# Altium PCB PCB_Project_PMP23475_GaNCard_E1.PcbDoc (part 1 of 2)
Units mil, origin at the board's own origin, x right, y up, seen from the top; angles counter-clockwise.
Board outline 1635 x 1330 mil, 6 copper layers (Top Layer, MidLayer1, MidLayer2, MidLayer3, MidLayer4, Bottom Layer), stack 78 mil thick; 80 components, 70 nets, 296 pads, 209 vias.
Unrouted connection lines stored in the file: 3.
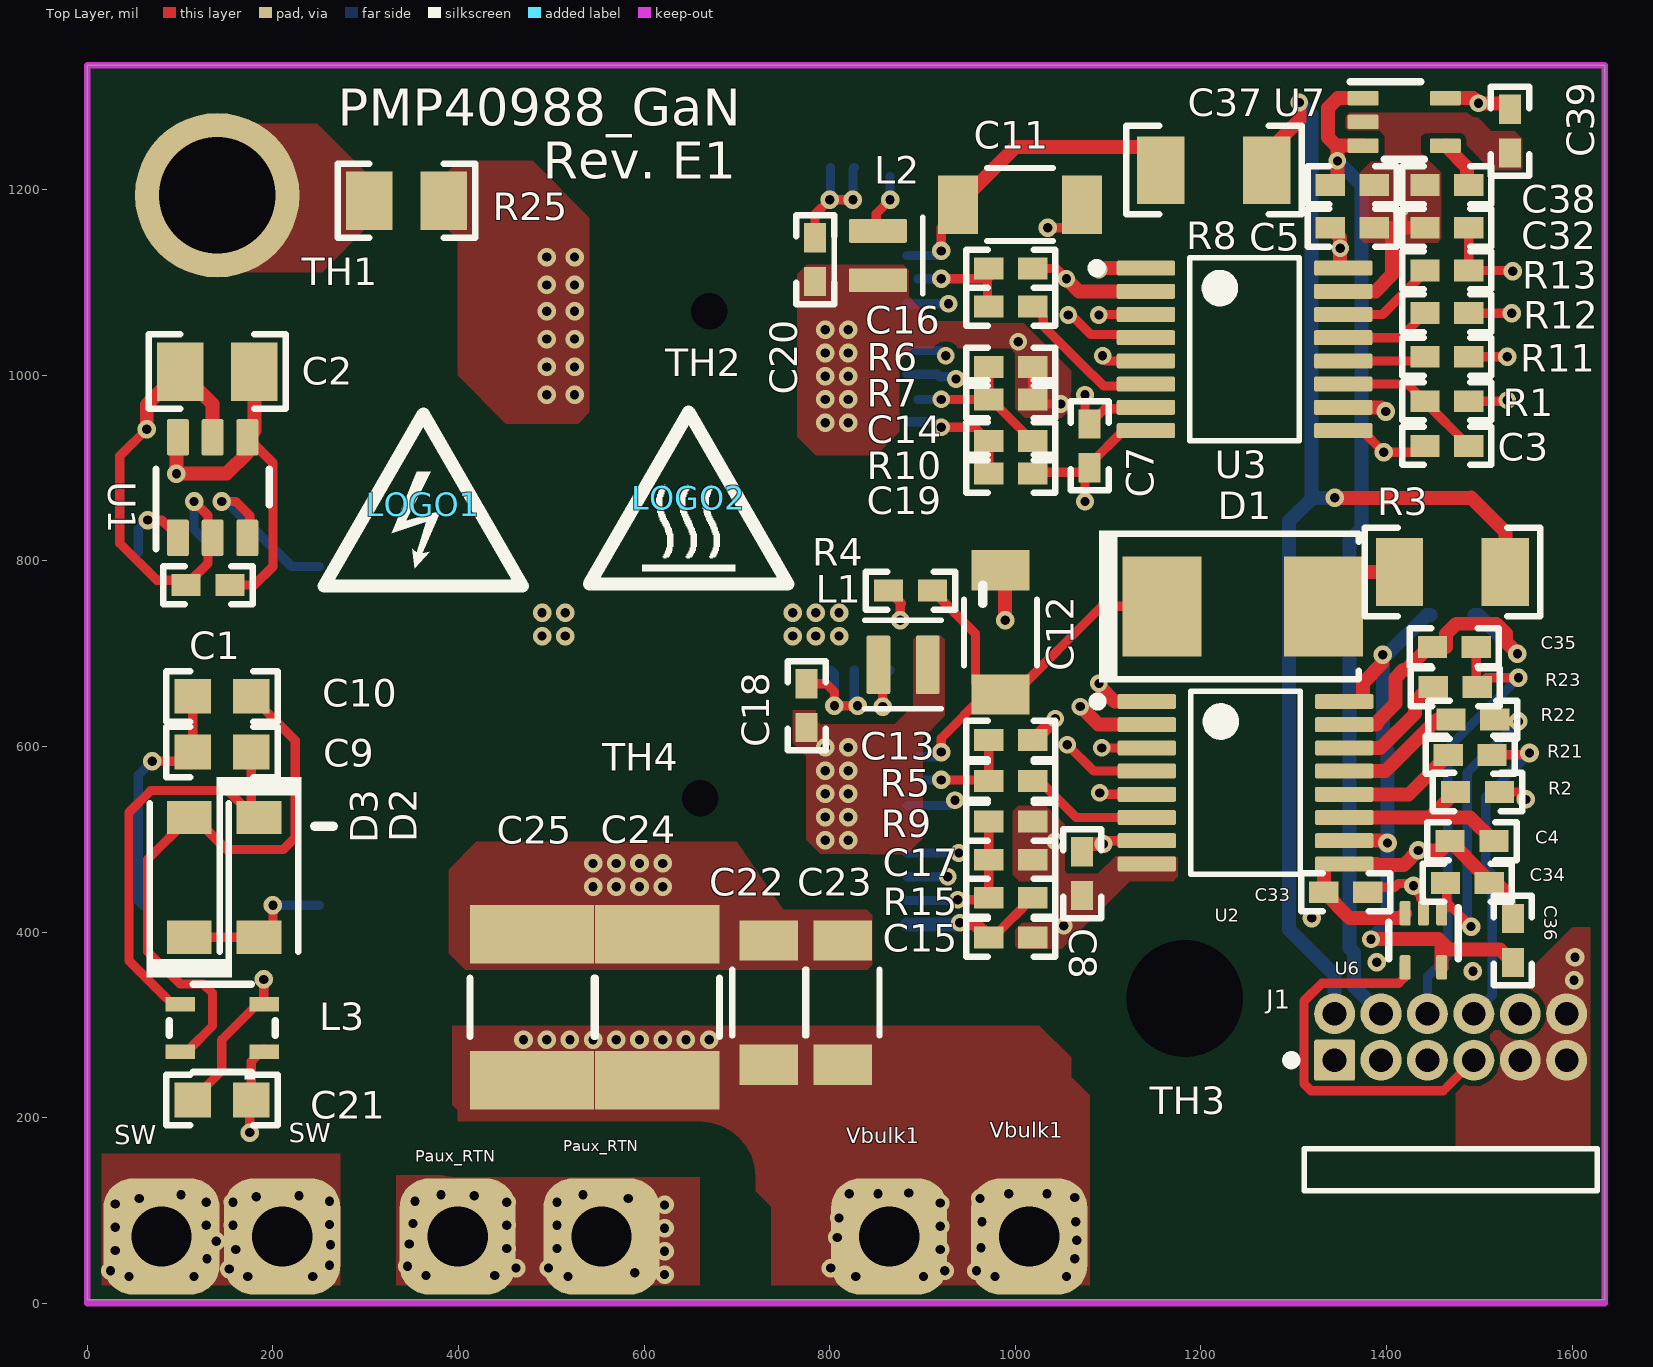
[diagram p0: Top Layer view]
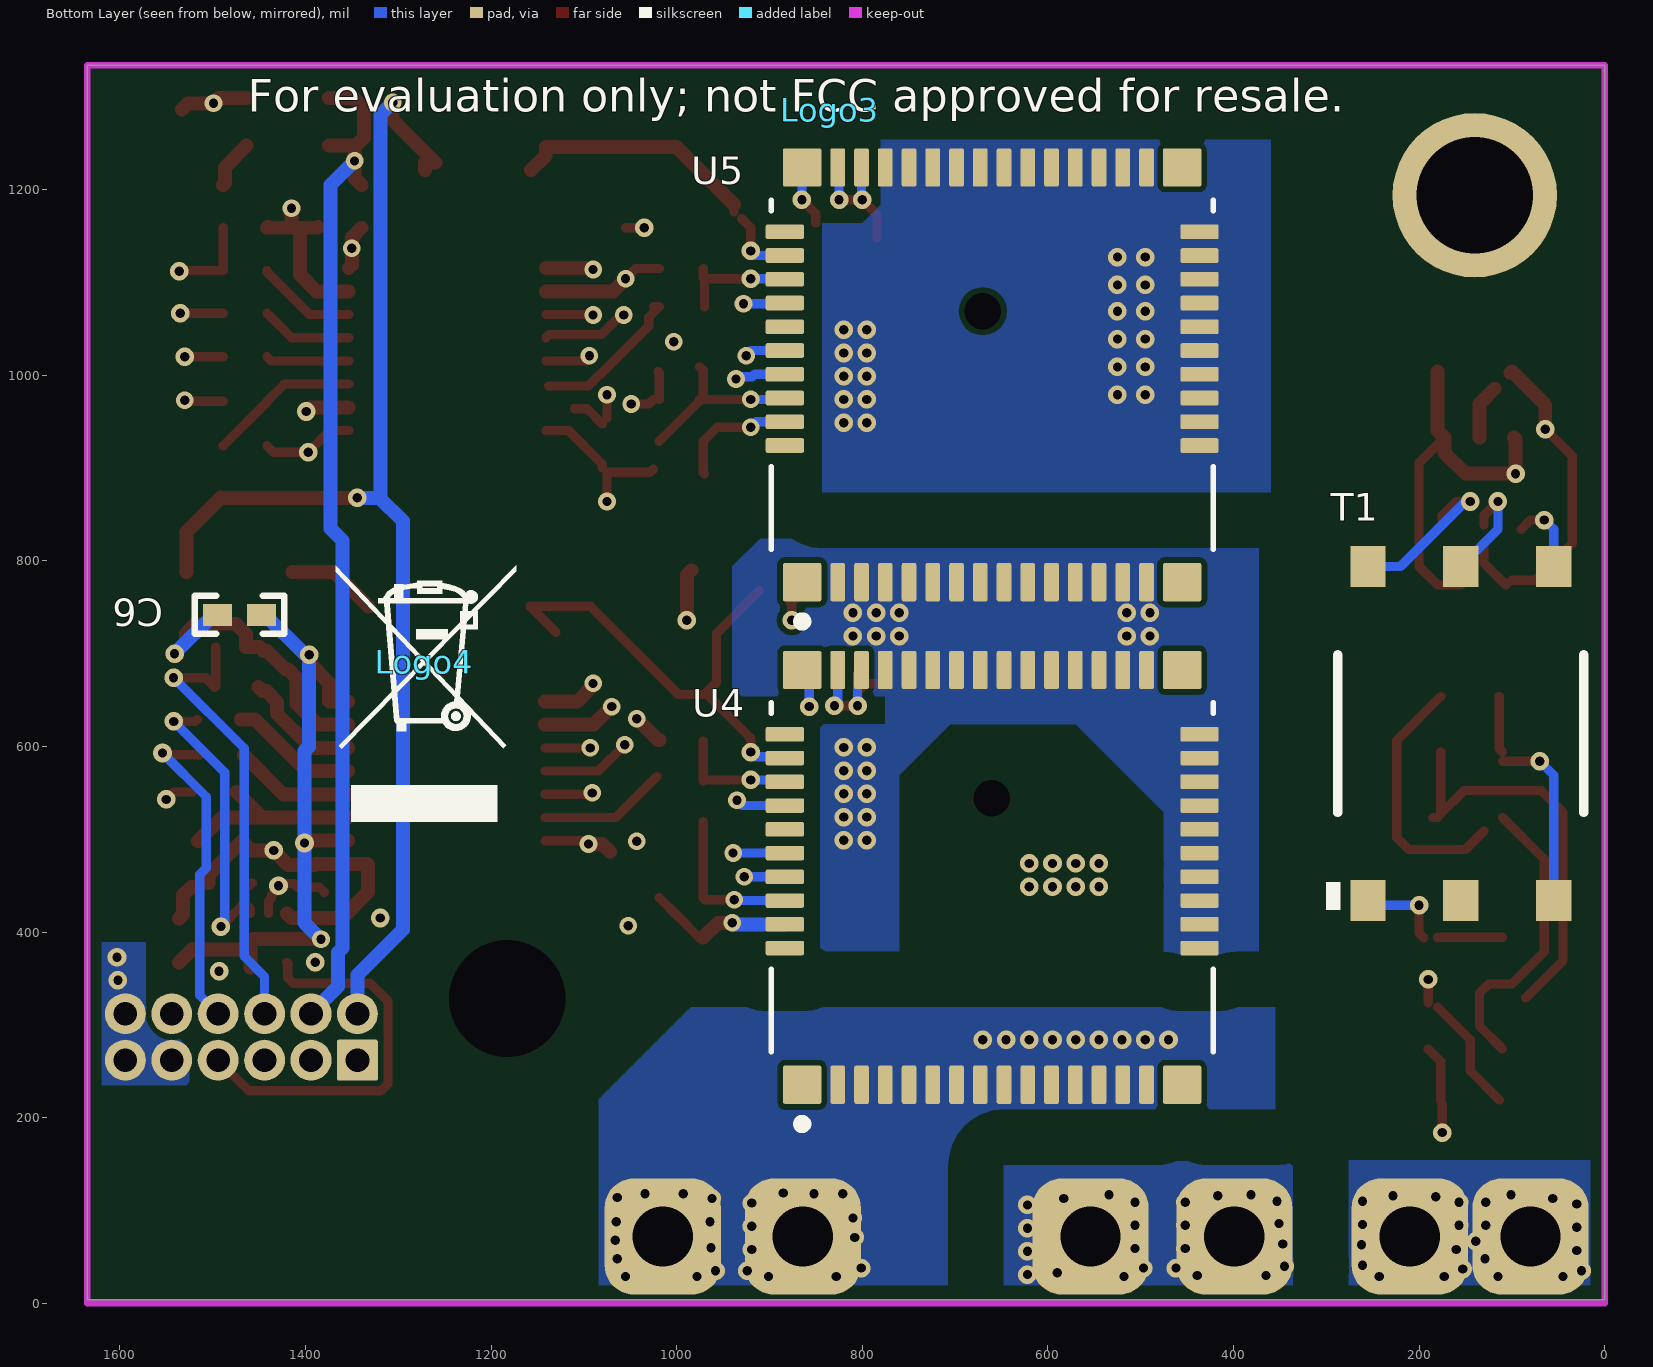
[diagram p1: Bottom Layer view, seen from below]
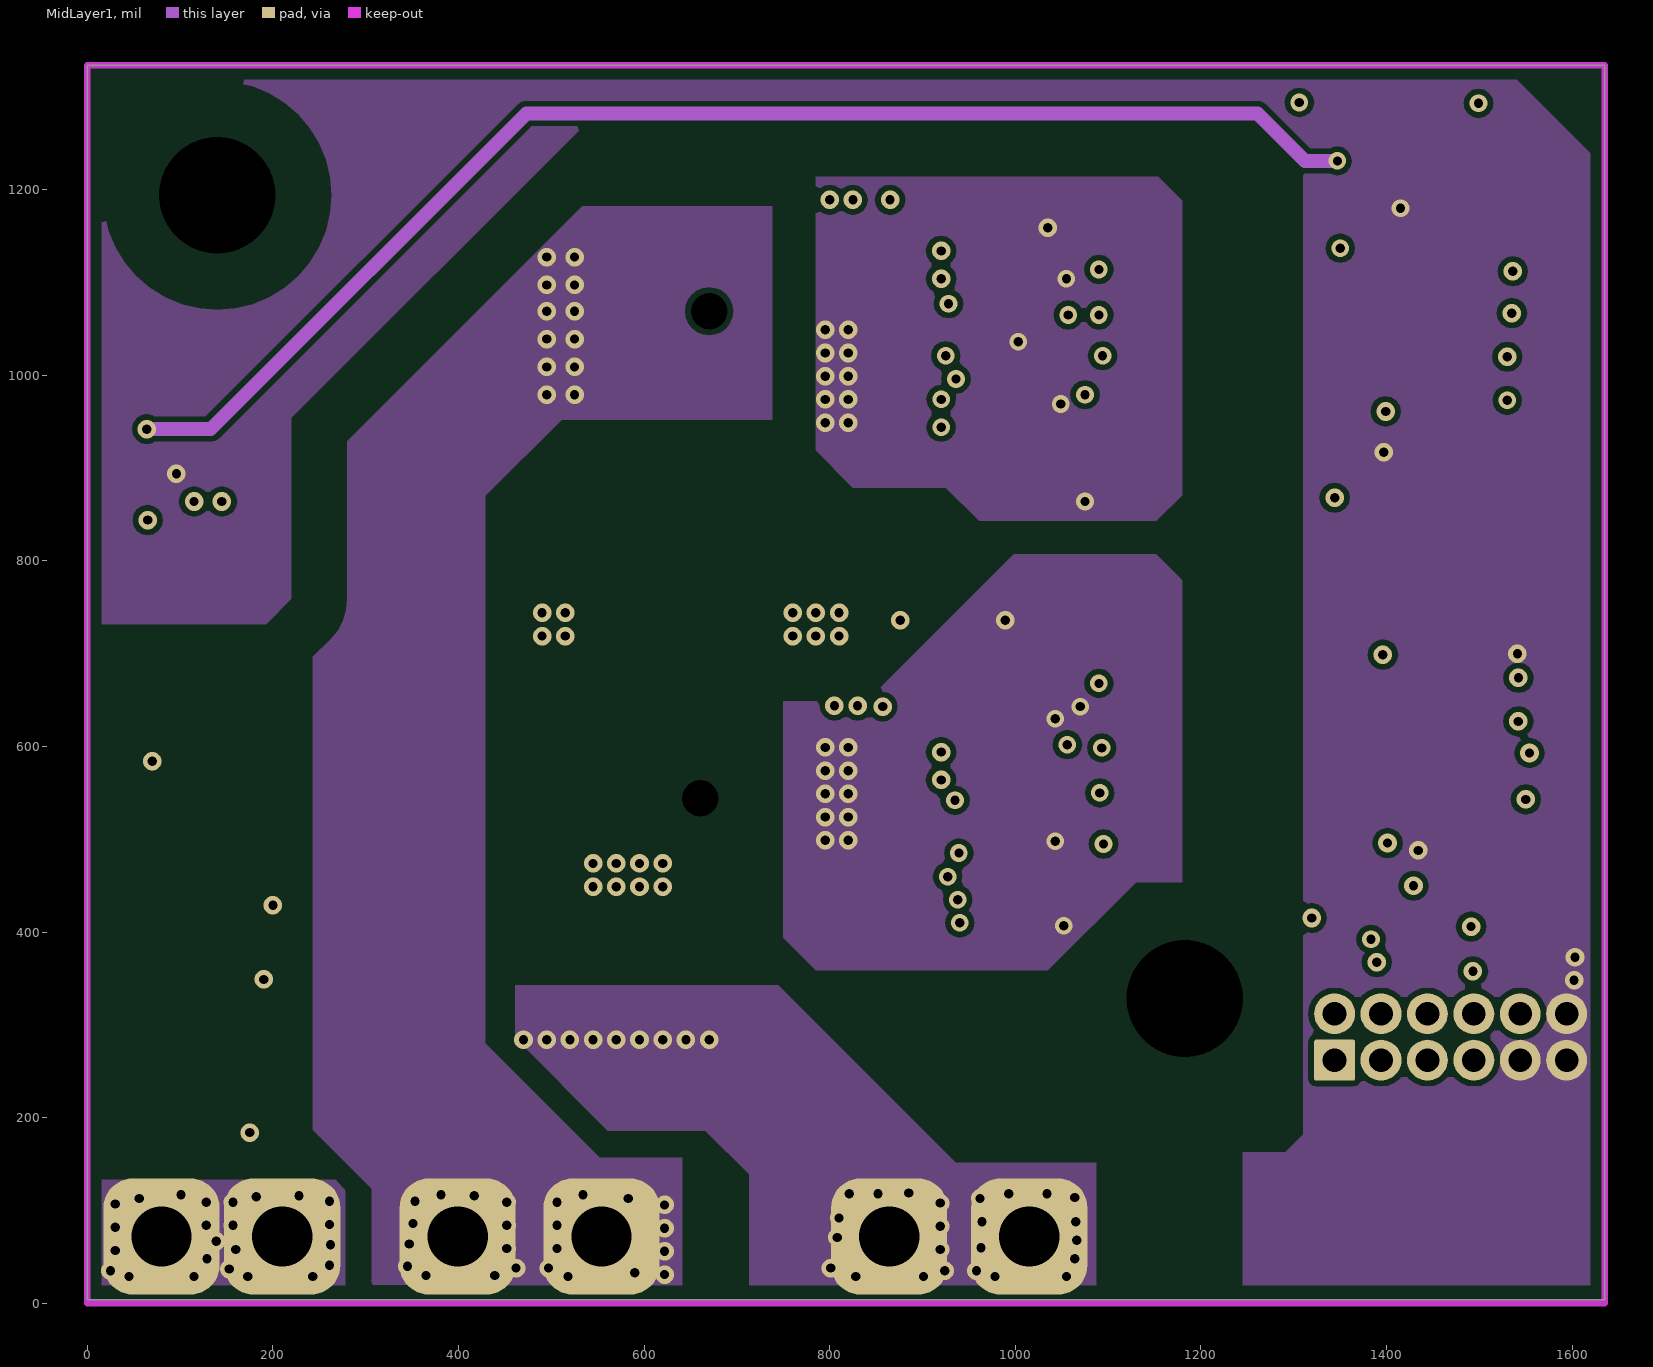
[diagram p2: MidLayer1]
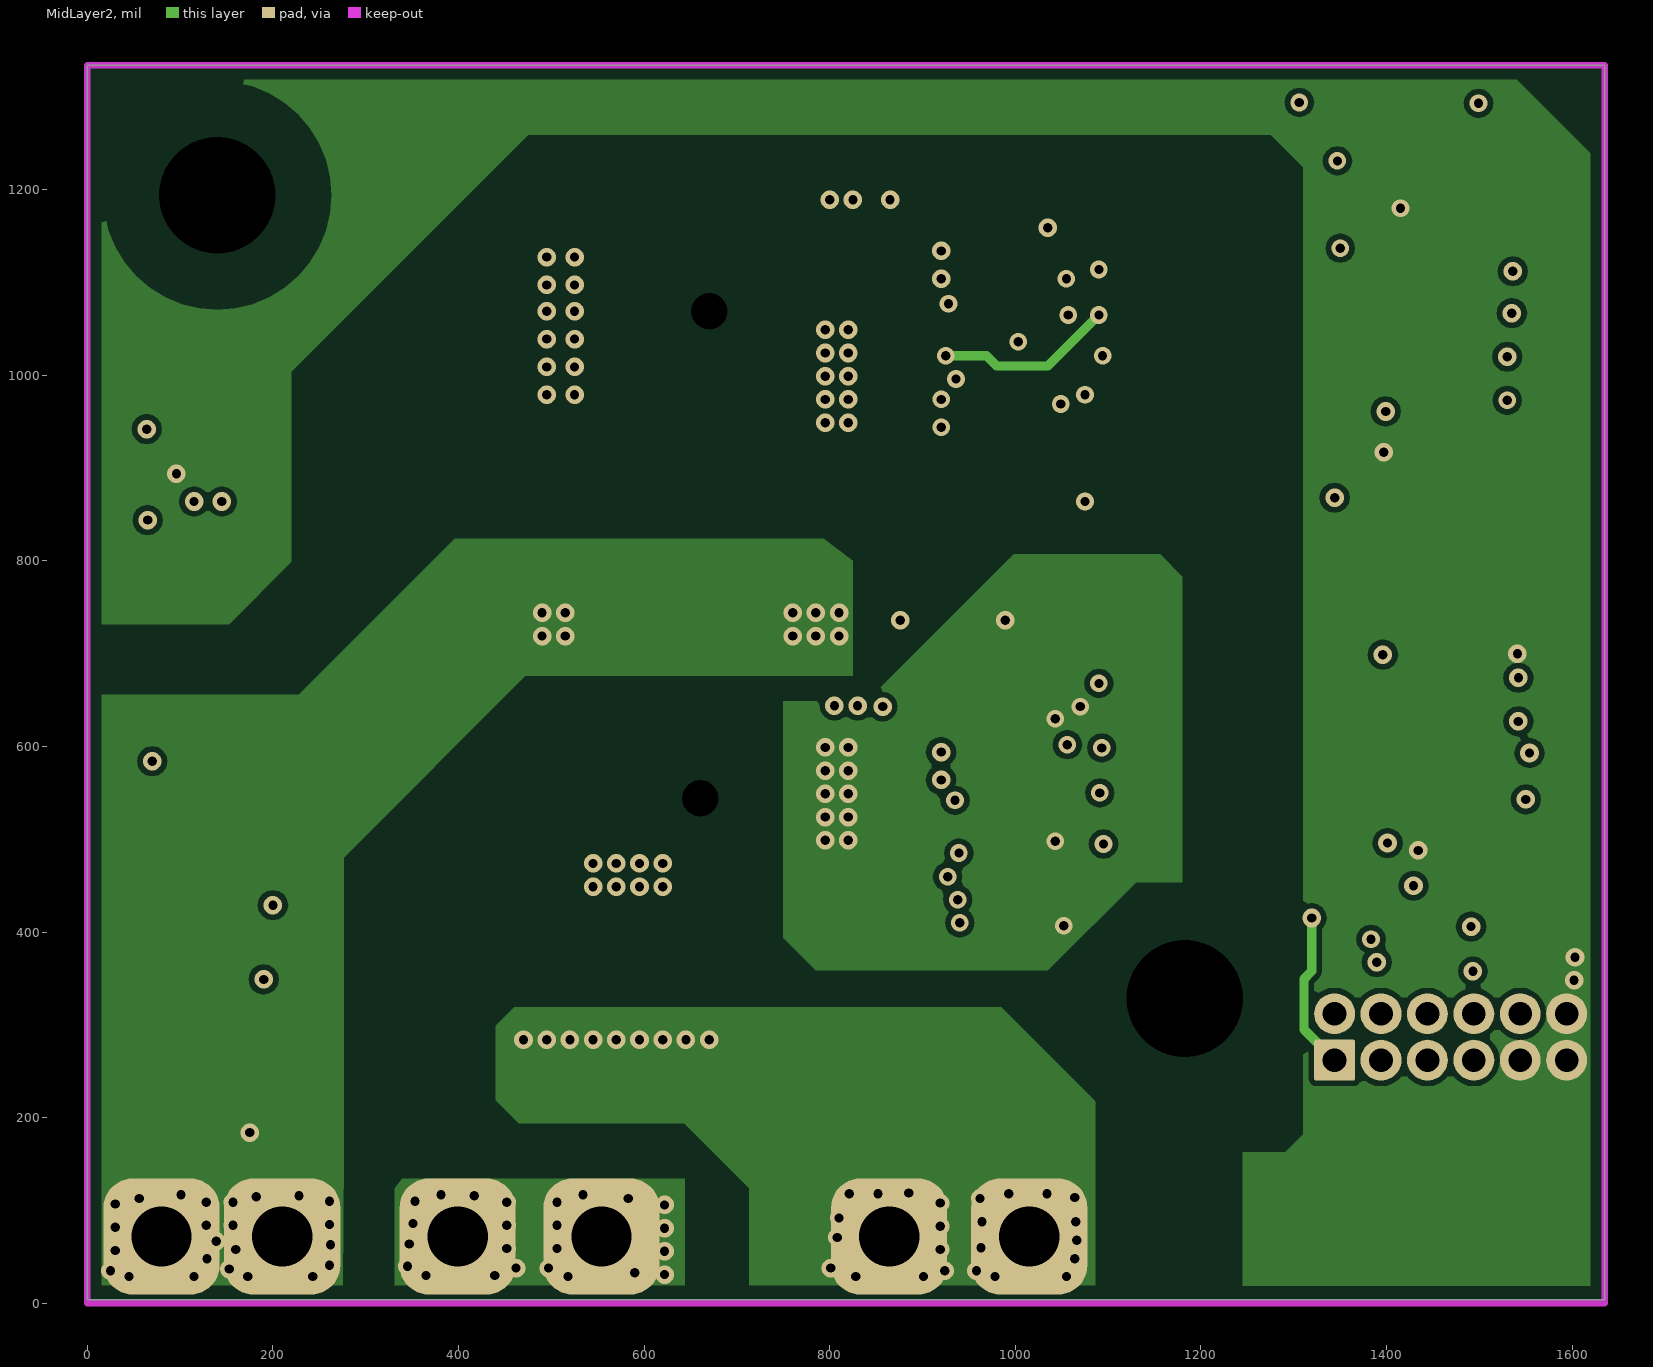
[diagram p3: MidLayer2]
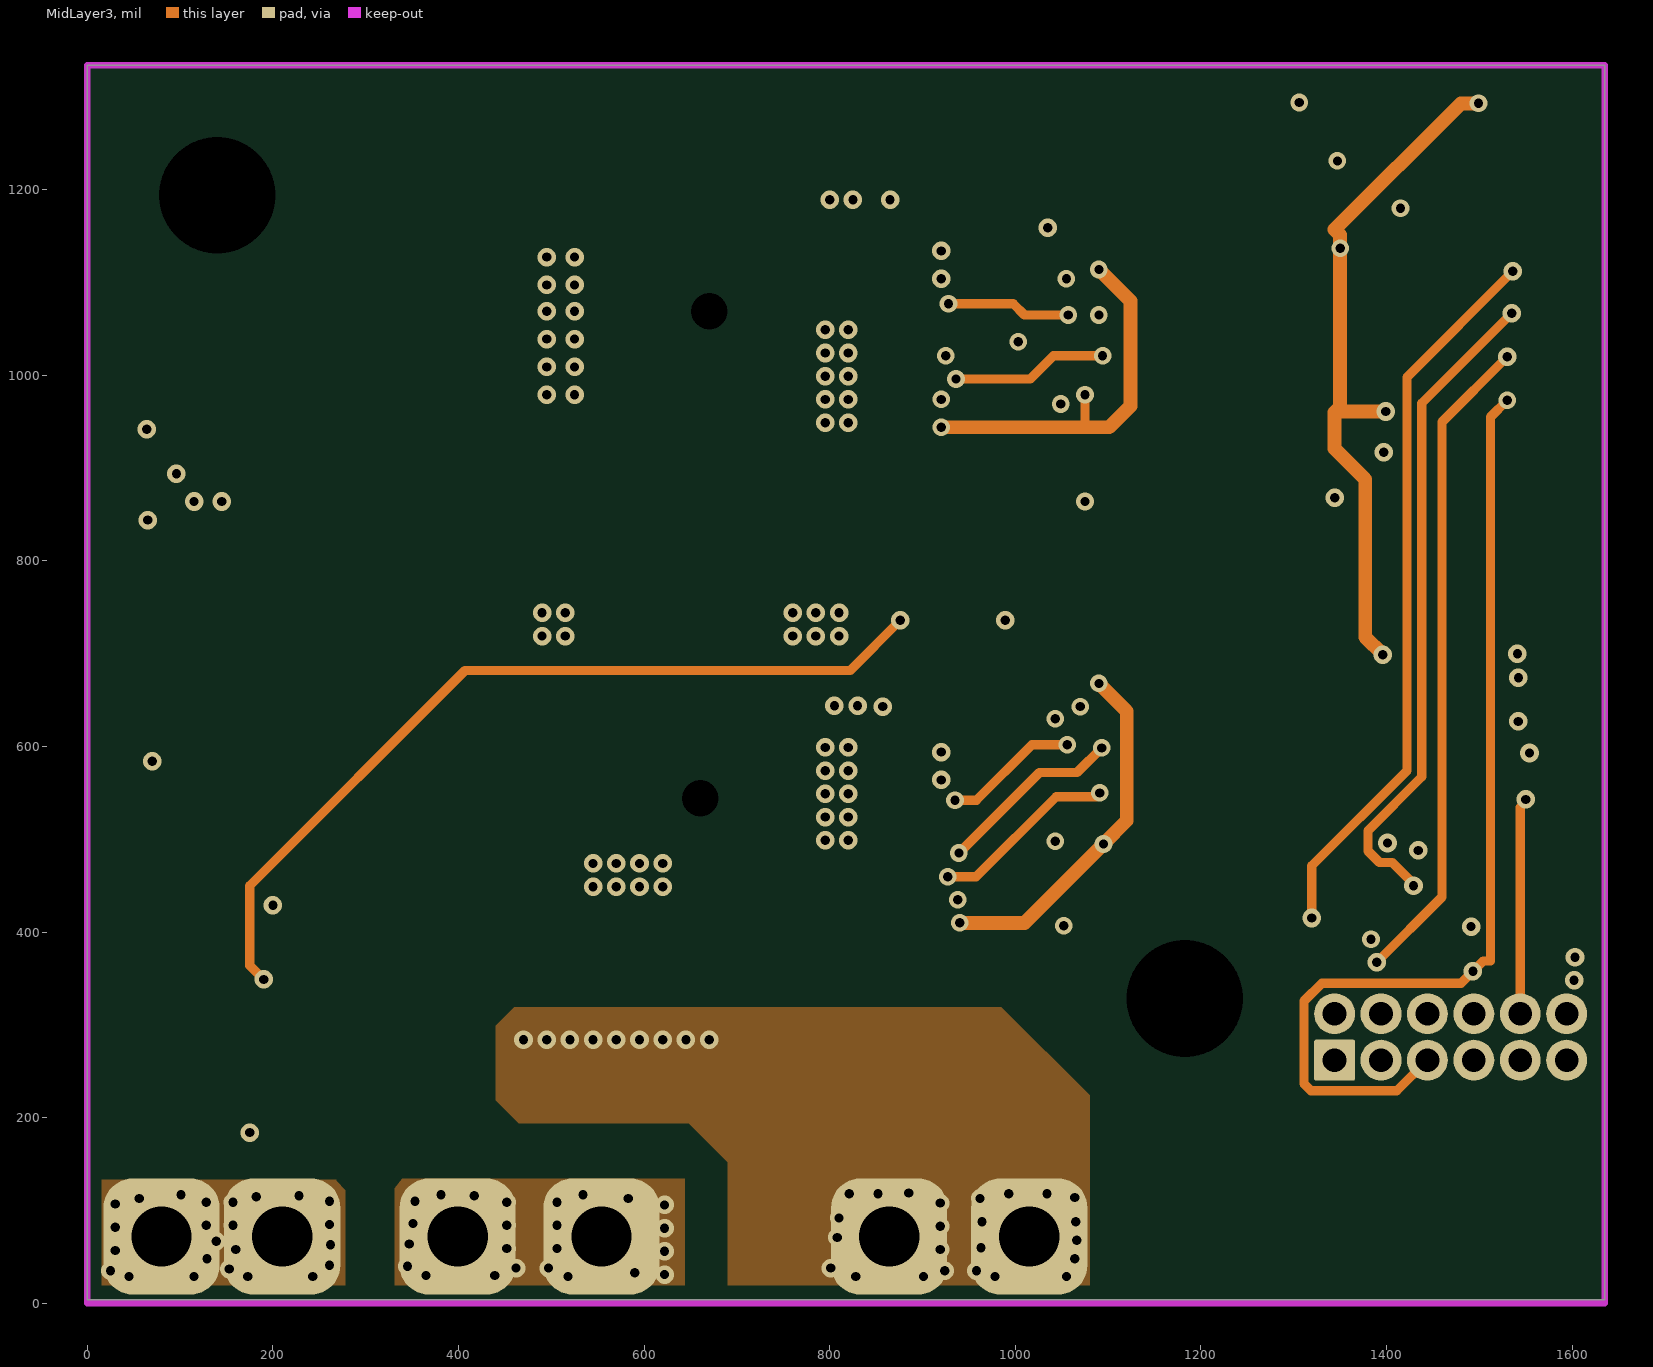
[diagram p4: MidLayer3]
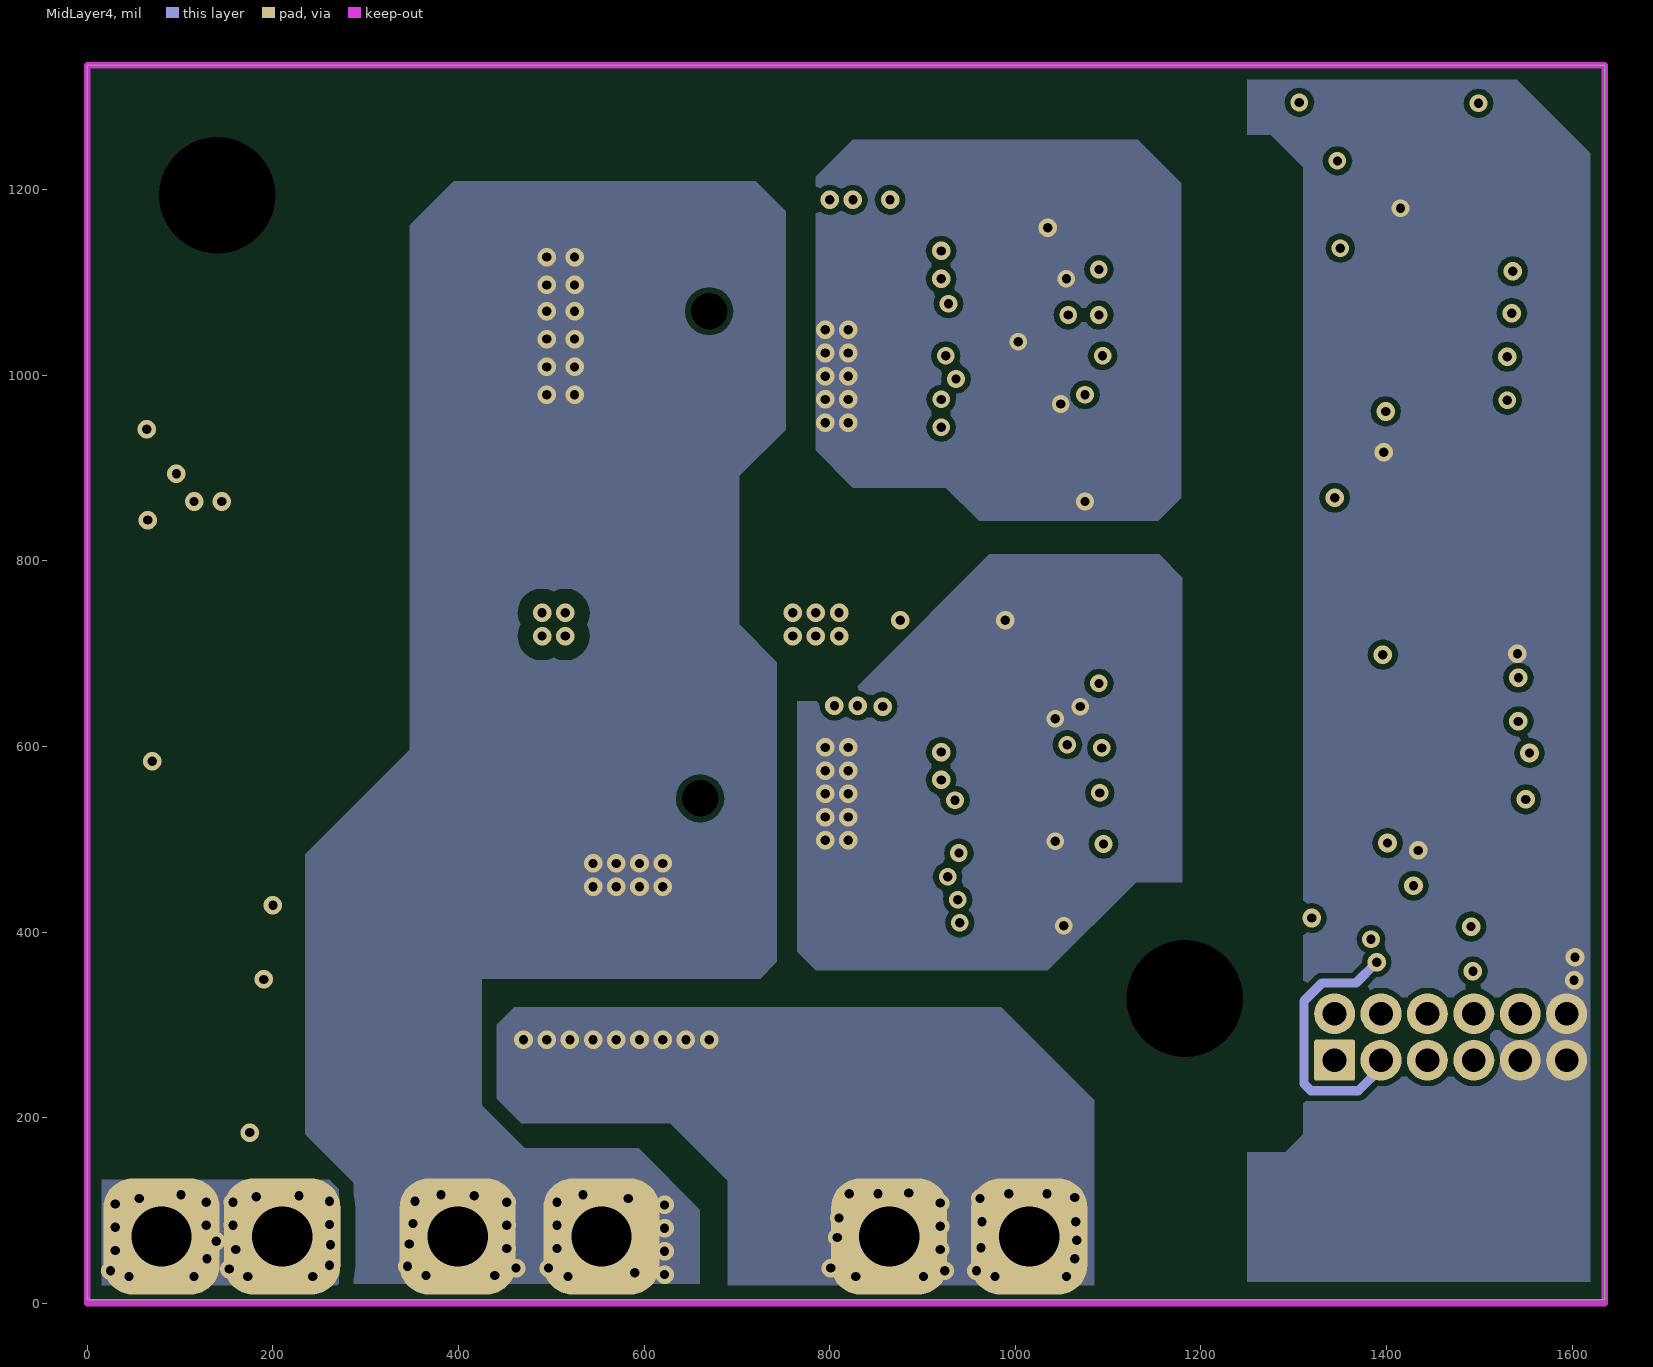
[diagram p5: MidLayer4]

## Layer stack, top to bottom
Top Solder: solder mask 0.4, Solder Resist, Dk 3.5
Top Layer: signal copper 2.8
Dielectric 1: prepreg 4.6, FR-4 High Tg, Dk 4.2
MidLayer1: signal copper 2.8
Dielectric 2: core 23.7, FR-4 High Tg, Dk 4.2
MidLayer2: signal copper 2.8
4.6: prepreg 4.6, FR-4 High Tg, Dk 4.2
MidLayer3: signal copper 2.8
Dielectric 4: core 23.7, Dk 4.2
MidLayer4: signal copper 2.8
Dielectric 5: prepreg 4.6, Dk 4.2
Bottom Layer: signal copper 2.8
Bottom Solder: solder mask 0.4, Solder Resist, Dk 3.5

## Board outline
0,4 1635,4 1635,1334 0,1334

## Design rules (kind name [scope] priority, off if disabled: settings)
AcuteAngle [All] p1: minimum=4.50000000000000E+0001 checktracksonly=FALSE
AssemblyTestPointUsage [All] p1: valid=2
BoardOutlineClearance [OnCopper] p1: gap=15 ignorepadtopadclearanceinfootprint=FALSE
Clearance "Clearance_Thermal Vias" [InNet('NC5')] p1: gap=20 ignorepadtopadclearanceinfootprint=FALSE
Clearance "Clearance_Thermal Vias_1" [InNet('NC6')] p2: gap=20 ignorepadtopadclearanceinfootprint=FALSE
Clearance Clearance_VSW_Mid1 [(OnMultiLayer Or OnMid) And InNetClass('VSWNET') vs OnMid And Not InNetClass('VSWNET')] p3: gap=16 ignorepadtopadclearanceinfootprint=TRUE
Clearance Clearance_Screw_Top [InNetClass('Screw') vs OnLayer('Top Layer') And Not InNetClass('Screw')] p4: gap=60 ignorepadtopadclearanceinfootprint=TRUE
Clearance Clearance_Screw_Bottom [InNetClass('Screw') vs OnLayer('Bottom Layer') And Not InNetClass('Screw')] p5: gap=60 ignorepadtopadclearanceinfootprint=TRUE
Clearance Clearance_Screw_Other [InNetClass('Screw') vs Not OnLayer('Top Layer')  AND Not InNetClass('Screw')] p6: gap=60 ignorepadtopadclearanceinfootprint=TRUE
Clearance Clearance_VSW_Mid2 [(OnMultiLayer Or OnMid) And Not InNetClass('VSWNET') vs OnMid And InNetClass('VSWNET')] p7: gap=16 ignorepadtopadclearanceinfootprint=TRUE
Clearance Clearance_VSW [InNetClass('VSWNET')   and OnCopper vs Not InNetClass('VSWNET') and OnCopper] p8: gap=60 ignorepadtopadclearanceinfootprint=TRUE
Clearance Clearance_VHV_Mid1 [(OnMultiLayer Or OnMid) And InNetClass('VHV') vs OnMid And Not InNetClass('VHV')] p9: gap=16 ignorepadtopadclearanceinfootprint=TRUE
Clearance Clearance_VHV_Mid2 [(OnMultiLayer Or OnMid) And Not InNetClass('VHV') vs OnMid And InNetClass('VHV')] p10: gap=16 ignorepadtopadclearanceinfootprint=TRUE
Clearance Clearance_VHV [InNetClass('VHV') vs Not InNetClass('VHV') and OnCopper] p11: gap=60 ignorepadtopadclearanceinfootprint=FALSE
Clearance Clearance_INGND [InNetClass('INGND') and OnCopper vs Not InNetClass('INGND')  and OnCopper] p12: gap=60 ignorepadtopadclearanceinfootprint=FALSE
Clearance [All] p13: gap=6 ignorepadtopadclearanceinfootprint=TRUE
ComponentClearance ComponentClearance_Shunt [InComponentClass('Header') vs InComponentClass('Shunt')] p1: gap=0 collisioncheckmode=3 verticalgap=0 showdistances=FALSE
ComponentClearance ComponentClearance_MountingHoles_FiducialMarks [InComponentClass('Mounting Holes') vs InComponentClass('FiducialMark')] p2 off: gap=50 collisioncheckmode=3 verticalgap=10 showdistances=FALSE
ComponentClearance ComponentClearance_Logo [InComponentClass('Logo')] p3: gap=0 collisioncheckmode=3 verticalgap=10 showdistances=FALSE
ComponentClearance ComponentClearance_ScrewToNut [(HasFootprint('NY PMS 440 0025 PH')) vs (HasFootprint('Keystone_1902C'))] p4: gap=5 collisioncheckmode=3 verticalgap=10 showdistances=FALSE
ComponentClearance ComponentClearance_MountingHoles [InComponentClass('Mounting Holes')] p5: gap=250 collisioncheckmode=3 verticalgap=100000 showdistances=FALSE
ComponentClearance ComponentClearance_SmallPassives [HasFootprint('0201*') or HasFootprint('0402*') or HasFootprint('0508') or HasFootprint('0603*') or HasFootprint('0612') or HasFootprint('0805*') or HasFootprint('0815*') or HasFootprint('0830*') or HasFootprint('1206*') or HasFootprint('1210*') or HasFootprint('1808*') or HasFootprint('1812*') or HasFootprint('1825*') or HasFootprint('2010*') or HasFootprint('2220*') or HasFootprint('2225*') or HasFootprint('2512*') or HasFootprint('2728*') or HasFootprint('3518*') vs HasFootprint('0201*') or HasFootprint('0402*') or HasFootprint('0508') or HasFootprint('0603*') or HasFootprint('0612') or HasFootprint('0805*') or HasFootprint('0815*') or HasFootprint('0830*') or HasFootprint('1206*') or HasFootprint('1210*') or HasFootprint('1808*') or HasFootprint('1812*') or HasFootprint('1825*') or HasFootprint('2010*') or HasFootprint('2220*') or HasFootprint('2225*') or HasFootprint('2512*') or HasFootprint('2728*') or HasFootprint('3518*')] p6: gap=1 collisioncheckmode=3 verticalgap=10 showdistances=FALSE
ComponentClearance ComponentClearance_THtoSMT [IsThruComponent vs IsSMTComponent] p7: gap=10 collisioncheckmode=3 verticalgap=30 showdistances=FALSE
ComponentClearance ComponentClearance_THtoTH [IsThruComponent vs IsThruComponent] p8 off: gap=74 collisioncheckmode=3 verticalgap=30 showdistances=FALSE
ComponentClearance [All] p9: gap=1 collisioncheckmode=3 verticalgap=10 showdistances=FALSE
DiffPairsRouting [All] p1: maxlimit=100 minlimit=10 mostfreqgap=10 substack1={A02F224D-4808-492E-A71F-5F5656FBF0D4} toplayer_{a02f224d-4808-492e-a71f-5f5656fbf0d4}_minwidth=15 toplayer_{a02f224d-4808-492e-a71f-5f5656fbf0d4}_maxwidth=15 toplayer_{a02f224d-4808-492e-a71f-5f5656fbf0d4}_prefwidth=15 midlayer1_{a02f224d-4808-492e-a71f-5f5656fbf0d4}_minwidth=15 midlayer1_{a02f224d-4808-492e-a71f-5f5656fbf0d4}_maxwidth=15 midlayer1_{a02f224d-4808-492e-a71f-5f5656fbf0d4}_prefwidth=15 midlayer2_{a02f224d-4808-492e-a71f-5f5656fbf0d4}_minwidth=15 midlayer2_{a02f224d-4808-492e-a71f-5f5656fbf0d4}_maxwidth=15 midlayer2_{a02f224d-4808-492e-a71f-5f5656fbf0d4}_prefwidth=15 midlayer3_{a02f224d-4808-492e-a71f-5f5656fbf0d4}_minwidth=15 midlayer3_{a02f224d-4808-492e-a71f-5f5656fbf0d4}_maxwidth=15 midlayer3_{a02f224d-4808-492e-a71f-5f5656fbf0d4}_prefwidth=15 midlayer4_{a02f224d-4808-492e-a71f-5f5656fbf0d4}_minwidth=15 midlayer4_{a02f224d-4808-492e-a71f-5f5656fbf0d4}_maxwidth=15 midlayer4_{a02f224d-4808-492e-a71f-5f5656fbf0d4}_prefwidth=15 bottomlayer_{a02f224d-4808-492e-a71f-5f5656fbf0d4}_minwidth=15 bottomlayer_{a02f224d-4808-492e-a71f-5f5656fbf0d4}_maxwidth=15 bottomlayer_{a02f224d-4808-492e-a71f-5f5656fbf0d4}_prefwidth=15 substack2={B838D286-A00B-4EE2-88E1-F79279CC64B4} toplayer_{b838d286-a00b-4ee2-88e1-f79279cc64b4}_minwidth=15 toplayer_{b838d286-a00b-4ee2-88e1-f79279cc64b4}_maxwidth=15 toplayer_{b838d286-a00b-4ee2-88e1-f79279cc64b4}_prefwidth=15 midlayer1_{b838d286-a00b-4ee2-88e1-f79279cc64b4}_minwidth=15 midlayer1_{b838d286-a00b-4ee2-88e1-f79279cc64b4}_maxwidth=15 midlayer1_{b838d286-a00b-4ee2-88e1-f79279cc64b4}_prefwidth=15 midlayer2_{b838d286-a00b-4ee2-88e1-f79279cc64b4}_minwidth=15 midlayer2_{b838d286-a00b-4ee2-88e1-f79279cc64b4}_maxwidth=15 midlayer2_{b838d286-a00b-4ee2-88e1-f79279cc64b4}_prefwidth=15 midlayer3_{b838d286-a00b-4ee2-88e1-f79279cc64b4}_minwidth=15 midlayer3_{b838d286-a00b-4ee2-88e1-f79279cc64b4}_maxwidth=15 midlayer3_{b838d286-a00b-4ee2-88e1-f79279cc64b4}_prefwidth=15 midlayer4_{b838d286-a00b-4ee2-88e1-f79279cc64b4}_minwidth=15 midlayer4_{b838d286-a00b-4ee2-88e1-f79279cc64b4}_maxwidth=15 midlayer4_{b838d286-a00b-4ee2-88e1-f79279cc64b4}_prefwidth=15 bottomlayer_{b838d286-a00b-4ee2-88e1-f79279cc64b4}_minwidth=15 bottomlayer_{b838d286-a00b-4ee2-88e1-f79279cc64b4}_maxwidth=15 bottomlayer_{b838d286-a00b-4ee2-88e1-f79279cc64b4}_prefwidth=15 substack3={88BCB183-C685-456E-B90A-365A53404C2C} toplayer_{88bcb183-c685-456e-b90a-365a53404c2c}_minwidth=15 toplayer_{88bcb183-c685-456e-b90a-365a53404c2c}_maxwidth=15 toplayer_{88bcb183-c685-456e-b90a-365a53404c2c}_prefwidth=15 midlayer1_{88bcb183-c685-456e-b90a-365a53404c2c}_minwidth=15 midlayer1_{88bcb183-c685-456e-b90a-365a53404c2c}_maxwidth=15 midlayer1_{88bcb183-c685-456e-b90a-365a53404c2c}_prefwidth=15 midlayer2_{88bcb183-c685-456e-b90a-365a53404c2c}_minwidth=15 midlayer2_{88bcb183-c685-456e-b90a-365a53404c2c}_maxwidth=15 midlayer2_{88bcb183-c685-456e-b90a-365a53404c2c}_prefwidth=15 midlayer3_{88bcb183-c685-456e-b90a-365a53404c2c}_minwidth=15 midlayer3_{88bcb183-c685-456e-b90a-365a53404c2c}_maxwidth=15 midlayer3_{88bcb183-c685-456e-b90a-365a53404c2c}_prefwidth=15 midlayer4_{88bcb183-c685-456e-b90a-365a53404c2c}_minwidth=15 midlayer4_{88bcb183-c685-456e-b90a-365a53404c2c}_maxwidth=15 midlayer4_{88bcb183-c685-456e-b90a-365a53404c2c}_prefwidth=15 bottomlayer_{88bcb183-c685-456e-b90a-365a53404c2c}_minwidth=15 bottomlayer_{88bcb183-c685-456e-b90a-365a53404c2c}_maxwidth=15 bottomlayer_{88bcb183-c685-456e-b90a-365a53404c2c}_prefwidth=15 substack4={4C8C2325-90D5-40B8-8B6B-4F66D44EFE25} toplayer_{4c8c2325-90d5-40b8-8b6b-4f66d44efe25}_minwidth=15 toplayer_{4c8c2325-90d5-40b8-8b6b-4f66d44efe25}_maxwidth=15 toplayer_{4c8c2325-90d5-40b8-8b6b-4f66d44efe25}_prefwidth=15 midlayer1_{4c8c2325-90d5-40b8-8b6b-4f66d44efe25}_minwidth=15 midlayer1_{4c8c2325-90d5-40b8-8b6b-4f66d44efe25}_maxwidth=15 midlayer1_{4c8c2325-90d5-40b8-8b6b-4f66d44efe25}_prefwidth=15 midlayer2_{4c8c2325-90d5-40b8-8b6b-4f66d44efe25}_minwidth=15 midlayer2_{4c8c2325-90d5-40b8-8b6b-4f66d44efe25}_maxwidth=15 midlayer2_{4c8c2325-90d5-40b8-8b6b-4f66d44efe25}_prefwidth=15 midlayer3_{4c8c2325-90d5-40b8-8b6b-4f66d44efe25}_minwidth=15 midlayer3_{4c8c2325-90d5-40b8-8b6b-4f66d44efe25}_maxwidth=15 midlayer3_{4c8c2325-90d5-40b8-8b6b-4f66d44efe25}_prefwidth=15 midlayer4_{4c8c2325-90d5-40b8-8b6b-4f66d44efe25}_minwidth=15 midlayer4_{4c8c2325-90d5-40b8-8b6b-4f66d44efe25}_maxwidth=15 midlayer4_{4c8c2325-90d5-40b8-8b6b-4f66d44efe25}_prefwidth=15 bottomlayer_{4c8c2325-90d5-40b8-8b6b-4f66d44efe25}_minwidth=15 bottomlayer_{4c8c2325-90d5-40b8-8b6b-4f66d44efe25}_maxwidth=15 bottomlayer_{4c8c2325-90d5-40b8-8b6b-4f66d44efe25}_prefwidth=15 toplayer_minwidth=15 toplayer_maxwidth=15 toplayer_prefwidth=15 midlayer1_minwidth=15 midlayer1_maxwidth=15 midlayer1_prefwidth=15 midlayer2_minwidth=15 midlayer2_maxwidth=15 midlayer2_prefwidth=15 midlayer3_minwidth=15 midlayer3_maxwidth=15 midlayer3_prefwidth=15 midlayer4_minwidth=15 midlayer4_maxwidth=15 midlayer4_prefwidth=15 bottomlayer_minwidth=15 bottomlayer_maxwidth=15 bottomlayer_prefwidth=15 substack5={553D66F5-99EF-40B1-BA7C-73E3B04B176F} toplayer_{553d66f5-99ef-40b1-ba7c-73e3b04b176f}_minwidth=15 toplayer_{553d66f5-99ef-40b1-ba7c-73e3b04b176f}_maxwidth=15 toplayer_{553d66f5-99ef-40b1-ba7c-73e3b04b176f}_prefwidth=15 midlayer1_{553d66f5-99ef-40b1-ba7c-73e3b04b176f}_minwidth=15 midlayer1_{553d66f5-99ef-40b1-ba7c-73e3b04b176f}_maxwidth=15 midlayer1_{553d66f5-99ef-40b1-ba7c-73e3b04b176f}_prefwidth=15 midlayer2_{553d66f5-99ef-40b1-ba7c-73e3b04b176f}_minwidth=15 midlayer2_{553d66f5-99ef-40b1-ba7c-73e3b04b176f}_maxwidth=15 midlayer2_{553d66f5-99ef-40b1-ba7c-73e3b04b176f}_prefwidth=15 midlayer3_{553d66f5-99ef-40b1-ba7c-73e3b04b176f}_minwidth=15 midlayer3_{553d66f5-99ef-40b1-ba7c-73e3b04b176f}_maxwidth=15 midlayer3_{553d66f5-99ef-40b1-ba7c-73e3b04b176f}_prefwidth=15 midlayer4_{553d66f5-99ef-40b1-ba7c-73e3b04b176f}_minwidth=15 midlayer4_{553d66f5-99ef-40b1-ba7c-73e3b04b176f}_maxwidth=15 midlayer4_{553d66f5-99ef-40b1-ba7c-73e3b04b176f}_prefwidth=15 bottomlayer_{553d66f5-99ef-40b1-ba7c-73e3b04b176f}_minwidth=15 bottomlayer_{553d66f5-99ef-40b1-ba7c-73e3b04b176f}_maxwidth=15 bottomlayer_{553d66f5-99ef-40b1-ba7c-73e3b04b176f}_prefwidth=15 substack6={FF0C9878-5A48-402E-B013-8E2EEFCEDCCB} toplayer_{ff0c9878-5a48-402e-b013-8e2eefcedccb}_minwidth=15 toplayer_{ff0c9878-5a48-402e-b013-8e2eefcedccb}_maxwidth=15 toplayer_{ff0c9878-5a48-402e-b013-8e2eefcedccb}_prefwidth=15 midlayer1_{ff0c9878-5a48-402e-b013-8e2eefcedccb}_minwidth=15 midlayer1_{ff0c9878-5a48-402e-b013-8e2eefcedccb}_maxwidth=15 midlayer1_{ff0c9878-5a48-402e-b013-8e2eefcedccb}_prefwidth=15 midlayer2_{ff0c9878-5a48-402e-b013-8e2eefcedccb}_minwidth=15 midlayer2_{ff0c9878-5a48-402e-b013-8e2eefcedccb}_maxwidth=15 midlayer2_{ff0c9878-5a48-402e-b013-8e2eefcedccb}_prefwidth=15 midlayer3_{ff0c9878-5a48-402e-b013-8e2eefcedccb}_minwidth=15 midlayer3_{ff0c9878-5a48-402e-b013-8e2eefcedccb}_maxwidth=15 midlayer3_{ff0c9878-5a48-402e-b013-8e2eefcedccb}_prefwidth=15 midlayer4_{ff0c9878-5a48-402e-b013-8e2eefcedccb}_minwidth=15 midlayer4_{ff0c9878-5a48-402e-b013-8e2eefcedccb}_maxwidth=15 midlayer4_{ff0c9878-5a48-402e-b013-8e2eefcedccb}_prefwidth=15 bottomlayer_{ff0c9878-5a48-402e-b013-8e2eefcedccb}_minwidth=15 bottomlayer_{ff0c9878-5a48-402e-b013-8e2eefcedccb}_maxwidth=15 bottomlayer_{ff0c9878-5a48-402e-b013-8e2eefcedccb}_prefwidth=15 substack7={5BB5B65B-6C7F-4868-A6AE-66DD57ADDCBD} toplayer_{5bb5b65b-6c7f-4868-a6ae-66dd57addcbd}_minwidth=15 toplayer_{5bb5b65b-6c7f-4868-a6ae-66dd57addcbd}_maxwidth=15 toplayer_{5bb5b65b-6c7f-4868-a6ae-66dd57addcbd}_prefwidth=15 midlayer1_{5bb5b65b-6c7f-4868-a6ae-66dd57addcbd}_minwidth=15 midlayer1_{5bb5b65b-6c7f-4868-a6ae-66dd57addcbd}_maxwidth=15 midlayer1_{5bb5b65b-6c7f-4868-a6ae-66dd57addcbd}_prefwidth=15 midlayer2_{5bb5b65b-6c7f-4868-a6ae-66dd57addcbd}_minwidth=15 midlayer2_{5bb5b65b-6c7f-4868-a6ae-66dd57addcbd}_maxwidth=15 midlayer2_{5bb5b65b-6c7f-4868-a6ae-66dd57addcbd}_prefwidth=15 midlayer3_{5bb5b65b-6c7f-4868-a6ae-66dd57addcbd}_minwidth=15 midlayer3_{5bb5b65b-6c7f-4868-a6ae-66dd57addcbd}_maxwidth=15 midlayer3_{5bb5b65b-6c7f-4868-a6ae-66dd57addcbd}_prefwidth=15 midlayer4_{5bb5b65b-6c7f-4868-a6ae-66dd57addcbd}_minwidth=15 midlayer4_{5bb5b65b-6c7f-4868-a6ae-66dd57addcbd}_maxwidth=15 midlayer4_{5bb5b65b-6c7f-4868-a6ae-66dd57addcbd}_prefwidth=15 bottomlayer_{5bb5b65b-6c7f-4868-a6ae-66dd57addcbd}_minwidth=15 bottomlayer_{5bb5b65b-6c7f-4868-a6ae-66dd57addcbd}_maxwidth=15 bottomlayer_{5bb5b65b-6c7f-4868-a6ae-66dd57addcbd}_prefwidth=15 substack8={590F0BEA-1E04-4904-B9C9-D9D160075BC2} toplayer_{590f0bea-1e04-4904-b9c9-d9d160075bc2}_minwidth=15 toplayer_{590f0bea-1e04-4904-b9c9-d9d160075bc2}_maxwidth=15 toplayer_{590f0bea-1e04-4904-b9c9-d9d160075bc2}_prefwidth=15 midlayer1_{590f0bea-1e04-4904-b9c9-d9d160075bc2}_minwidth=15 midlayer1_{590f0bea-1e04-4904-b9c9-d9d160075bc2}_maxwidth=15 midlayer1_{590f0bea-1e04-4904-b9c9-d9d160075bc2}_prefwidth=15 midlayer2_{590f0bea-1e04-4904-b9c9-d9d160075bc2}_minwidth=15 midlayer2_{590f0bea-1e04-4904-b9c9-d9d160075bc2}_maxwidth=15 midlayer2_{590f0bea-1e04-4904-b9c9-d9d160075bc2}_prefwidth=15 midlayer3_{590f0bea-1e04-4904-b9c9-d9d160075bc2}_minwidth=15 midlayer3_{590f0bea-1e04-4904-b9c9-d9d160075bc2}_maxwidth=15 midlayer3_{590f0bea-1e04-4904-b9c9-d9d160075bc2}_prefwidth=15 midlayer4_{590f0bea-1e04-4904-b9c9-d9d160075bc2}_minwidth=15 midlayer4_{590f0bea-1e04-4904-b9c9-d9d160075bc2}_maxwidth=15 midlayer4_{590f0bea-1e04-4904-b9c9-d9d160075bc2}_prefwidth=15 bottomlayer_{590f0bea-1e04-4904-b9c9-d9d160075bc2}_minwidth=15 bottomlayer_{590f0bea-1e04-4904-b9c9-d9d160075bc2}_maxwidth=15 bottomlayer_{590f0bea-1e04-4904-b9c9-d9d160075bc2}_prefwidth=15 substack9={B2AC4F48-1A5F-44D7-A91B-3BAADFDAAED0} toplayer_{b2ac4f48-1a5f-44d7-a91b-3baadfdaaed0}_minwidth=15 toplayer_{b2ac4f48-1a5f-44d7-a91b-3baadfdaaed0}_maxwidth=15 toplayer_{b2ac4f48-1a5f-44d7-a91b-3baadfdaaed0}_prefwidth=15 midlayer1_{b2ac4f48-1a5f-44d7-a91b-3baadfdaaed0}_minwidth=15 midlayer1_{b2ac4f48-1a5f-44d7-a91b-3baadfdaaed0}_maxwidth=15 midlayer1_{b2ac4f48-1a5f-44d7-a91b-3baadfdaaed0}_prefwidth=15 midlayer2_{b2ac4f48-1a5f-44d7-a91b-3baadfdaaed0}_minwidth=15 midlayer2_{b2ac4f48-1a5f-44d7-a91b-3baadfdaaed0}_maxwidth=15 midlayer2_{b2ac4f48-1a5f-44d7-a91b-3baadfdaaed0}_prefwidth=15 midlayer3_{b2ac4f48-1a5f-44d7-a91b-3baadfdaaed0}_minwidth=15 midlayer3_{b2ac4f48-1a5f-44d7-a91b-3baadfdaaed0}_maxwidth=15 midlayer3_{b2ac4f48-1a5f-44d7-a91b-3baadfdaaed0}_prefwidth=15 midlayer4_{b2ac4f48-1a5f-44d7-a91b-3baadfdaaed0}_minwidth=15 midlayer4_{b2ac4f48-1a5f-44d7-a91b-3baadfdaaed0}_maxwidth=15 midlayer4_{b2ac4f48-1a5f-44d7-a91b-3baadfdaaed0}_prefwidth=15 bottomlayer_{b2ac4f48-1a5f-44d7-a91b-3baadfdaaed0}_minwidth=15 bottomlayer_{b2ac4f48-1a5f-44d7-a91b-3baadfdaaed0}_maxwidth=15 bottomlayer_{b2ac4f48-1a5f-44d7-a91b-3baadfdaaed0}_prefwidth=15 substack10={DD3D4156-A54D-4E1F-B7FF-E5EF72C45496} toplayer_{dd3d4156-a54d-4e1f-b7ff-e5ef72c45496}_minwidth=15 toplayer_{dd3d4156-a54d-4e1f-b7ff-e5ef72c45496}_maxwidth=15 toplayer_{dd3d4156-a54d-4e1f-b7ff-e5ef72c45496}_prefwidth=15 midlayer1_{dd3d4156-a54d-4e1f-b7ff-e5ef72c45496}_minwidth=15 midlayer1_{dd3d4156-a54d-4e1f-b7ff-e5ef72c45496}_maxwidth=15 midlayer1_{dd3d4156-a54d-4e1f-b7ff-e5ef72c45496}_prefwidth=15 midlayer2_{dd3d4156-a54d-4e1f-b7ff-e5ef72c45496}_minwidth=15 midlayer2_{dd3d4156-a54d-4e1f-b7ff-e5ef72c45496}_maxwidth=15 midlayer2_{dd3d4156-a54d-4e1f-b7ff-e5ef72c45496}_prefwidth=15 midlayer3_{dd3d4156-a54d-4e1f-b7ff-e5ef72c45496}_minwidth=15 midlayer3_{dd3d4156-a54d-4e1f-b7ff-e5ef72c45496}_maxwidth=15 midlayer3_{dd3d4156-a54d-4e1f-b7ff-e5ef72c45496}_prefwidth=15 midlayer4_{dd3d4156-a54d-4e1f-b7ff-e5ef72c45496}_minwidth=15 midlayer4_{dd3d4156-a54d-4e1f-b7ff-e5ef72c45496}_maxwidth=15 midlayer4_{dd3d4156-a54d-4e1f-b7ff-e5ef72c45496}_prefwidth=15 bottomlayer_{dd3d4156-a54d-4e1f-b7ff-e5ef72c45496}_minwidth=15 bottomlayer_{dd3d4156-a54d-4e1f-b7ff-e5ef72c45496}_maxwidth=15 bottomlayer_{dd3d4156-a54d-4e1f-b7ff-e5ef72c45496}_prefwidth=15 substack11={7CC4AE65-1EB7-43C1-8FCA-3677EE54F737} toplayer_{7cc4ae65-1eb7-43c1-8fca-3677ee54f737}_minwidth=15 toplayer_{7cc4ae65-1eb7-43c1-8fca-3677ee54f737}_maxwidth=15 toplayer_{7cc4ae65-1eb7-43c1-8fca-3677ee54f737}_prefwidth=15 midlayer1_{7cc4ae65-1eb7-43c1-8fca-3677ee54f737}_minwidth=15 midlayer1_{7cc4ae65-1eb7-43c1-8fca-3677ee54f737}_maxwidth=15 midlayer1_{7cc4ae65-1eb7-43c1-8fca-3677ee54f737}_prefwidth=15 midlayer2_{7cc4ae65-1eb7-43c1-8fca-3677ee54f737}_minwidth=15 midlayer2_{7cc4ae65-1eb7-43c1-8fca-3677ee54f737}_maxwidth=15 midlayer2_{7cc4ae65-1eb7-43c1-8fca-3677ee54f737}_prefwidth=15 midlayer3_{7cc4ae65-1eb7-43c1-8fca-3677ee54f737}_minwidth=15 midlayer3_{7cc4ae65-1eb7-43c1-8fca-3677ee54f737}_maxwidth=15 midlayer3_{7cc4ae65-1eb7-43c1-8fca-3677ee54f737}_prefwidth=15 midlayer4_{7cc4ae65-1eb7-43c1-8fca-3677ee54f737}_minwidth=15 midlayer4_{7cc4ae65-1eb7-43c1-8fca-3677ee54f737}_maxwidth=15 midlayer4_{7cc4ae65-1eb7-43c1-8fca-3677ee54f737}_prefwidth=15 bottomlayer_{7cc4ae65-1eb7-43c1-8fca-3677ee54f737}_minwidth=15 bottomlayer_{7cc4ae65-1eb7-43c1-8fca-3677ee54f737}_maxwidth=15 bottomlayer_{7cc4ae65-1eb7-43c1-8fca-3677ee54f737}_prefwidth=15 substack12={E8C37195-128A-4AA0-B681-9B6788FCEC2F} toplayer_{e8c37195-128a-4aa0-b681-9b6788fcec2f}_minwidth=15 toplayer_{e8c37195-128a-4aa0-b681-9b6788fcec2f}_maxwidth=15 toplayer_{e8c37195-128a-4aa0-b681-9b6788fcec2f}_prefwidth=15 midlayer1_{e8c37195-128a-4aa0-b681-9b6788fcec2f}_minwidth=15 midlayer1_{e8c37195-128a-4aa0-b681-9b6788fcec2f}_maxwidth=15 midlayer1_{e8c37195-128a-4aa0-b681-9b6788fcec2f}_prefwidth=15 midlayer2_{e8c37195-128a-4aa0-b681-9b6788fcec2f}_minwidth=15 midlayer2_{e8c37195-128a-4aa0-b681-9b6788fcec2f}_maxwidth=15 midlayer2_{e8c37195-128a-4aa0-b681-9b6788fcec2f}_prefwidth=15 midlayer3_{e8c37195-128a-4aa0-b681-9b6788fcec2f}_minwidth=15 midlayer3_{e8c37195-128a-4aa0-b681-9b6788fcec2f}_maxwidth=15 midlayer3_{e8c37195-128a-4aa0-b681-9b6788fcec2f}_prefwidth=15 midlayer4_{e8c37195-128a-4aa0-b681-9b6788fcec2f}_minwidth=15 midlayer4_{e8c37195-128a-4aa0-b681-9b6788fcec2f}_maxwidth=15 midlayer4_{e8c37195-128a-4aa0-b681-9b6788fcec2f}_prefwidth=15 bottomlayer_{e8c37195-128a-4aa0-b681-9b6788fcec2f}_minwidth=15 bottomlayer_{e8c37195-128a-4aa0-b681-9b6788fcec2f}_maxwidth=15 bottomlayer_{e8c37195-128a-4aa0-b681-9b6788fcec2f}_prefwidth=15 substack13={92E0C252-34CC-4501-B85F-B111C59C3287} toplayer_{92e0c252-34cc-4501-b85f-b111c59c3287}_minwidth=15 toplayer_{92e0c252-34cc-4501-b85f-b111c59c3287}_maxwidth=15 toplayer_{92e0c252-34cc-4501-b85f-b111c59c3287}_prefwidth=15 midlayer1_{92e0c252-34cc-4501-b85f-b111c59c3287}_minwidth=15 midlayer1_{92e0c252-34cc-4501-b85f-b111c59c3287}_maxwidth=15 midlayer1_{92e0c252-34cc-4501-b85f-b111c59c3287}_prefwidth=15 midlayer2_{92e0c252-34cc-4501-b85f-b111c59c3287}_minwidth=15 midlayer2_{92e0c252-34cc-4501-b85f-b111c59c3287}_maxwidth=15 midlayer2_{92e0c252-34cc-4501-b85f-b111c59c3287}_prefwidth=15 midlayer3_{92e0c252-34cc-4501-b85f-b111c59c3287}_minwidth=15 midlayer3_{92e0c252-34cc-4501-b85f-b111c59c3287}_maxwidth=15 midlayer3_{92e0c252-34cc-4501-b85f-b111c59c3287}_prefwidth=15 midlayer4_{92e0c252-34cc-4501-b85f-b111c59c3287}_minwidth=15 midlayer4_{92e0c252-34cc-4501-b85f-b111c59c3287}_maxwidth=15 midlayer4_{92e0c252-34cc-4501-b85f-b111c59c3287}_prefwidth=15 bottomlayer_{92e0c252-34cc-4501-b85f-b111c59c3287}_minwidth=15 bottomlayer_{92e0c252-34cc-4501-b85f-b111c59c3287}_maxwidth=15 bottomlayer_{92e0c252-34cc-4501-b85f-b111c59c3287}_prefwidth=15 substack14={732F7058-E977-446F-8A06-ECA871B5D75E} toplayer_{732f7058-e977-446f-8a06-eca871b5d75e}_minwidth=15 toplayer_{732f7058-e977-446f-8a06-eca871b5d75e}_maxwidth=15 toplayer_{732f7058-e977-446f-8a06-eca871b5d75e}_prefwidth=15 midlayer1_{732f7058-e977-446f-8a06-eca871b5d75e}_minwidth=15 midlayer1_{732f7058-e977-446f-8a06-eca871b5d75e}_maxwidth=15 midlayer1_{732f7058-e977-446f-8a06-eca871b5d75e}_prefwidth=15 midlayer2_{732f7058-e977-446f-8a06-eca871b5d75e}_minwidth=15 midlayer2_{732f7058-e977-446f-8a06-eca871b5d75e}_maxwidth=15 midlayer2_{732f7058-e977-446f-8a06-eca871b5d75e}_prefwidth=15 midlayer3_{732f7058-e977-446f-8a06-eca871b5d75e}_minwidth=15 midlayer3_{732f7058-e977-446f-8a06-eca871b5d75e}_maxwidth=15 midlayer3_{732f7058-e977-446f-8a06-eca871b5d75e}_prefwidth=15 midlayer4_{732f7058-e977-446f-8a06-eca871b5d75e}_minwidth=15 midlayer4_{732f7058-e977-446f-8a06-eca871b5d75e}_maxwidth=15 midlayer4_{732f7058-e977-446f-8a06-eca871b5d75e}_prefwidth=15 bottomlayer_{732f7058-e977-446f-8a06-eca871b5d75e}_minwidth=15 bottomlayer_{732f7058-e977-446f-8a06-eca871b5d75e}_maxwidth=15 bottomlayer_{732f7058-e977-446f-8a06-eca871b5d75e}_prefwidth=15 maxuncoupledlength=1000
FabricationTestPointUsage TestPointUsage [All] p1: valid=2 allowmultiple=FALSE
FabricationTestpoint Testpoint [All] p1: side=3 testpointundercomponent=TRUE minsize=40 maxsize=100 preferedsize=60 minholesize=0 maxholesize=40 preferedholesize=32 testpointgrid=1 allowsidetop=TRUE allowsidebottom=TRUE usegrid=TRUE gridtolerance=0.01
FanoutControl Fanout_LCC [IsLCC] p1: bgadir=Out bgaviamode=Centered fanoutstyle=Auto fanoutdirection=Alternating viagrid=1 // Fanout_LCC (Default Rule)
FanoutControl Fanout_BGA [IsBGA] p2: bgadir=Out bgaviamode=Centered fanoutstyle=Auto fanoutdirection=Alternating viagrid=1 // Fanout_BGA (Default Rule)
FanoutControl Fanout_Default [All] p4: bgadir=Out bgaviamode=Centered fanoutstyle=Auto fanoutdirection=Alternating viagrid=1 // Fanout_Default (Default Rule)
FanoutControl Fanout_Small [(CompPinCount < 5)] p5: bgadir=Out bgaviamode=Centered fanoutstyle=Auto fanoutdirection=OutThenIn viagrid=1 // Fanout_Small (Default Rule)
HoleSize [All] p1: absolutevalues=TRUE maxlimit=251 minlimit=6 maxpercent=80.000 minpercent=20.000
MinimumAnnularRing MinimumAnnularRing_ThermalPadVias [IsVia and InAnyComponent] p1: minimumring=4.5
MinimumAnnularRing [IsVia] p2: minimumring=4.5
MinimumSolderMaskSliver MinimumSolderMaskSliver_Logo [InComponentClass('Logo') vs InComponentClass('Logo')] p1: minsoldermaskwidth=0.7
MinimumSolderMaskSliver [All] p2 off: minsoldermaskwidth=3.94
PlaneConnect [All] p1: planeconnectstyle=Relief reliefexpansion=10 reliefentries=4 reliefconductorwidth=10 reliefairgap=10
PolygonConnect [All] p1: connectstyle=Direct reliefconductorwidth=10 reliefentries=4 polygonreliefangle="90 Angle" airgapwidth=10
RoutingVias ThermalPadVias [IsVia and InAnyComponent] p1: holewidth=7.87 width=19.68 viastyle="Through Hole" minholewidth=7.87 minwidth=19.68 maxholewidth=12.99 maxwidth=23.62
RoutingVias [All] p2: holewidth=10 width=20 viastyle="Through Hole" minholewidth=6 minwidth=10 maxholewidth=40 maxwidth=65
SMDToCorner [All] p1: distance=30000
SilkToBoardRegionClearance [Not ((IsComment or IsDesignator) And (Hide <> 'False')) and not InRegion(1000,500,4000,800)] p1:
SilkToSilkClearance [All] p1: silktosilkclearance=0
SilkToSolderMaskClearance SilkscreenOverComponentPads [IsPad] p1: minsilkscreentomaskgap=5 clearancetoexposedcopper=TRUE
SolderMaskExpansion [All] p1: expansion=1.97 istentingtop=FALSE
Width [All] p1: maxlimit=1000 minlimit=6 preferedwidth=10 substack1={A02F224D-4808-492E-A71F-5F5656FBF0D4} substack2={B838D286-A00B-4EE2-88E1-F79279CC64B4} substack3={88BCB183-C685-456E-B90A-365A53404C2C} substack4={4C8C2325-90D5-40B8-8B6B-4F66D44EFE25} substack5={553D66F5-99EF-40B1-BA7C-73E3B04B176F} substack6={FF0C9878-5A48-402E-B013-8E2EEFCEDCCB} substack7={5BB5B65B-6C7F-4868-A6AE-66DD57ADDCBD} substack8={590F0BEA-1E04-4904-B9C9-D9D160075BC2} substack9={B2AC4F48-1A5F-44D7-A91B-3BAADFDAAED0} substack10={DD3D4156-A54D-4E1F-B7FF-E5EF72C45496} substack11={7CC4AE65-1EB7-43C1-8FCA-3677EE54F737} substack12={E8C37195-128A-4AA0-B681-9B6788FCEC2F} substack13={92E0C252-34CC-4501-B85F-B111C59C3287} substack14={732F7058-E977-446F-8A06-ECA871B5D75E} checkconnectedcopper=TRUE
15 further rules are at their usual default settings.

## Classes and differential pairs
net class VSWNET: 5V_H FAULT_HS ISO_12V_H NCT1 NCU61 NCU527 NCU543 NCU547 NCU552 NCU616 NetC9_1 NetC9_2 NetC10_2 NetC12_1 NetC13_2 NetC17_2 NetC18_1 NetD2_2 NetL1_2 NetR5_2 SW TEMP_HS ZVS_HS
net class VHV: HVBUS NCU51 NCU516
net class PGND: 5V_L FAULT_LS NCU627 NCU643 NCU647 NCU652 NetC11_1 NetC14_2 NetC16_2 NetC20_1 NetL2_2 NetR6_1 PGND TEMP_LS ZVS_LS
net class INGND: 3.3V 5V 12V AGND GaN_F HS_FAULT HS_PWM HS_TEMP HS_ZVS LS_FAULT LS_PWM LS_TEMP LS_ZVS NetC3_1 NetC4_1 NetC38_1 NetD1_2 NetR11_1 NetR12_1 NetR13_1 NetR21_1 NetR22_1 NetR23_1 NetT1_4 NetT1_6

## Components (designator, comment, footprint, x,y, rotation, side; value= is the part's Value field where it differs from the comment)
C1 "C1005X7R1H104K050BB" 0402 130,774 r0 top value=0.1uF
C2 "GCM21BR71C475KA73L" 0805_HV 140,1004 r0 top value=4.7uF
C3 "04025A101FAT2A" 0402 1465,924 r180 top value=100pF
C4 "04025A101FAT2A" 0402 1492,498 r180 top value=100pF
C5 "C1005X5R1E105K050BC" 0402 1363,1159 r0 top value=1uF
C6 "C1005X5R1E105K050BC" 0402 1471,741.74 r0 bottom value=1uF
C7 "C1005X5R1E105K050BC" 0402 1080,924 r90 top value=1uF
C8 "C1005X5R1E105K050BC" 0402 1072,463 r270 top value=1uF
C9 "C1608X5R1V475K080AC" 0603 145,594 r180 top value=4.7uF
C10 "C1608X5R1V475K080AC" 0603 145,654 r0 top value=4.7uF
C11 "C3216X7R1E106M160AE" 1206_190 1005,1184 r0 top value=10uF
C12 "C3216X7R1E106M160AE" 1206_190 984,723 r90 top value=10uF
C13 "04025A101FAT2A" 0402 995,607 r180 top value=100pF
C14 "04025A101FAT2A" 0402 995,974 r180 top value=100pF
C15 "CL05B224KO5NNNC" 0402 995,394 r180 top value=0.22uF
C16 "04025A101FAT2A" 0402 995,1115 r180 top value=100pF
C17 "04025A101FAT2A" 0402 995,478 r180 top value=100pF
C18 "GRT155R61E225KE13D" 0402 775,644 r270 top value=2.2uF
C19 "CL05B224KO5NNNC" 0402 995,894 r180 top value=0.22uF
C20 "GRT155R61E225KE13D" 0402 784.19,1124.63 r270 top value=2.2uF
C21 "C1608X5R1V475K080AC" 0603 145,219 r0 top value=4.7uF
C22 "C1206C223KDRACTU" 1206_190 734.19,324 r90 top value=0.022uF
C23 "C1206C223KDRACTU" 1206_190 814.19,324 r90 top value=0.022uF
C24 "C1812W104KDRACTU" 1812_254 614.19,319 r90 top value=0.1uF
C25 "C1812W104KDRACTU" 1812_254 479.19,319 r90 top value=0.1uF
C32 "GCQ1555C1H430JB01D" 0402 1465,1159 r180 top value=43pF
C33 "GCQ1555C1H430JB01D" 0402 1356,443 r180 top value=43pF
C34 "GCQ1555C1H430JB01D" 0402 1487,453 r0 top value=43pF
C35 "GCQ1555C1H430JB01D" 0402 1473,707 r180 top value=43pF
C36 "C1005X7R1H104K050BB" 0402 1536,391 r90 top value=0.1uF
C37 "C1005X7R1H104K050BB" 0402 1363,1205 r0 top value=0.1uF
C38 "C0402C103K4RACTU" 0402 1465,1205 r180 top value=0.01uF
C39 "C1005X5R1E105K050BC" 0402 1533,1263 r90 top value=1uF
D1 "GB01SLT06-214" SMB 1245,751 r0 top value=650V
D2 "MBR0520LT1G" SOD-123 185,459 r270 top value=20V
D3 "MBR0520LT1G" SOD-123 110,459 r90 top value=20V
J1 "M50-3900642" FP-M50-3900642_HDR12-MFG 1469,143.89 r0 top
L1 "SDEM20161T-4R7MS" FP-SDEM20161T-4R7MS_SMD2-MFG 879,688 r180 top
L2 "SDEM20161T-4R7MS" FP-SDEM20161T-4R7MS_SMD2-MFG 852,1129 r90 top
L3 "ACM2520-601-2P-T002" TDK_ACM2520-2P 145.49,296.5 r180 top
LOGO1 "DANGER HIGH VOLTAGE" IEC_HighVoltage_Small 362,861 r0 top
LOGO2 "CAUTION HOT SURFACE" IEC_HotSurface_Small 648,868 r0 top
Logo3 "FCC disclaimer" FCC_disclaimer 835,1286 r180 bottom
Logo4 "WEEE logo" WEEE_Minimum 1272,691 r180 bottom
Paux_RTN "3621-0-32-15-00-00-08-0" Mill-Max_3621-0-32-xx-00-00-08-0 399,-22 r0 top
Paux_RTN "3621-0-32-15-00-00-08-0" Mill-Max_3621-0-32-xx-00-00-08-0 554,-22 r0 top
R1 "RC0402FR-0749R9L" 0402 1465,972 r180 top value=49.9
R2 "RC0402FR-0749R9L" 0402 1498,551 r180 top value=49.9
R3 "CRCW12061R80JNEA" 1206 1471,788 r180 top value=1.8
R4 "ERJ-2GE0R00X" 0402 887,768 r0 top value=0
R5 "RC0402FR-0749R9L" 0402 995,563 r0 top value=49.9
R6 "RC0402FR-0749R9L" 0402 995,1074 r180 top value=49.9
R7 "CRCW040220K0FKED" 0402 995,1009 r180 top value=20.0k
R8 "ERJ-8GEY0R00V" 1206 1214,1221 r180 top value=0
R9 "CRCW040220K0FKED" 0402 995,519 r180 top value=20.0k
R10 "ERJ-2GE0R00X" 0402 995,929 r0 top value=0
R11 "CRCW0402300RJNED" 0402 1465,1020 r0 top value=300
R12 "CRCW0402300RJNED" 0402 1465,1067 r0 top value=300
R13 "CRCW040220R0FKED" 0402 1465,1113 r0 top value=20.0
R15 "ERJ-2GE0R00X" 0402 995,437 r180 top value=0
R21 "CRCW0402300RJNED" 0402 1490,591 r0 top value=300
R22 "CRCW0402300RJNED" 0402 1493,629 r0 top value=300
R23 "CRCW040220R0FKED" 0402 1474,664 r0 top value=20.0
R25 "RC0805JR-070RL" 0805_HV 344,1188 r180 top value=0
SW "3621-0-32-15-00-00-08-0" Mill-Max_3621-0-32-xx-00-00-08-0 80,-22 r0 top
SW "3621-0-32-15-00-00-08-0" Mill-Max_3621-0-32-xx-00-00-08-0 210,-22 r0 top
T1 "760390014" Wurth_760390013 155,614 r90 bottom value=475uH
TH1 "" TP_H045P075#1 158.86,694.79 r90 top
TH2 "" TP_H045P075#2 670,980.03 r90 top
TH3 "" TP_H045P075#3 1167.13,289 r90 top
TH4 "" TP_H045P075#4 680,544 r90 top
U1 "SN6505BDBVR" DBV0006A_N 135,879 r90 top
U2 "ISO7741FDBQR" DBQ0016A-MFG 1248,561 r0 top
U3 "ISO7741FDBQR" DBQ0016A-MFG 1247,1028 r0 top
U4 "LMG3525R030Q" RQS0052A-MFG 660,459 r90 bottom
U5 "LMG3525R030Q" RQS0052A-MFG 660,1000.5 r90 bottom
U6 "SN74AHC1G08DRLR" DRL0005A 1439.68,391.13 r270 top
U7 "TPS71733DCKT" DCK0005A_N 1419,1273 r0 top
Vbulk1 "3621-0-32-15-00-00-08-0" Mill-Max_3621-0-32-xx-00-00-08-0 864,-22 r0 top
Vbulk1 "3621-0-32-15-00-00-08-0" Mill-Max_3621-0-32-xx-00-00-08-0 1015,-22 r0 top

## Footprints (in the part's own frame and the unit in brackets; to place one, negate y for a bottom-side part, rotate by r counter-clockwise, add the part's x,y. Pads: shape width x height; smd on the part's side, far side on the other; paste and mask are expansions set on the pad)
0402 [mm] "0402 from SM-752 data"
  rect 0.8x0.6 smd: 1(-0.6,0) 2(0.6,0)
  silkscreen extent -1.22,-0.52 1.22,0.52, body extent -0.55,-0.3 0.55,0.3, height 0.6
0603 [mm] "0603 from SM-752 data"
  rect 1x0.95 smd: 1(-0.8,0) 2(0.8,0)
  silkscreen extent -1.52,-0.69 1.52,0.69, body extent -0.87,-0.47 0.87,0.47, height 1
0805_HV [mil] "0805 with 30mil clearance between pads"
  rect 50x63 smd: 1(-40,0) 2(40,0)
  silkscreen extent -74,-40 74,40, body extent -43,-29 43,29, height 57
1206 [mm] "1206 from SM-752 data"
  rect 1.3x1.85 smd: 1(-1.45,0) 2(1.45,0)
  silkscreen extent -2.4,-1.21 2.4,1.21, body extent -1.7,-0.9 1.7,0.9, height 1.35
1206_190 [mm] "1206_190"
  rect 1.1x1.6 smd: 1(-1.7,0) 2(1.7,0)
  silkscreen extent -0.9,-1 0.9,1, body extent -1.75,-0.95 1.75,0.95, height 1.9
1812_254 [mm] "SMD, 2-Leads, Body 4.8x3.4mm"
  rect 1.6x3.4 smd: 1(-2,0) 2(2,0)
  silkscreen extent -0.8,-1.7 0.8,1.7, body extent -2.4,-1.7 2.4,1.7, height 2.54
DBQ0016A-MFG [mm]
  rrect24% 1.6x0.41 smd paste+0 mask+0: 1(-2.7,2.222) 2(-2.7,1.587) 3(-2.7,0.953) 4(-2.7,0.318) 5(-2.7,-0.318) 6(-2.7,-0.953) 7(-2.7,-1.587) 8(-2.7,-2.222) 9(2.7,-2.222) 10(2.7,-1.587) 11(2.7,-0.953) 12(2.7,-0.318) 13(2.7,0.318) 14(2.7,0.953) 15(2.7,1.587) 16(2.7,2.222)
  silkscreen extent -4.17,-2.5 1.5,2.5, body extent -3.6,-2.75 3.6,2.75, height 0.25
DBV0006A_N [mm] "SOT23, 6-Leads, Body 2.9x1.6mm, Pitch 0.95mm, Lead Span 2.8mm, IPC Medium Density"
  rrect17% 1x0.6 smd: 1(-1.375,0.95) 2(-1.375,0) 3(-1.375,-0.95) 4(1.375,-0.95) 5(1.375,0) 6(1.375,0.95)
  silkscreen extent -1.68,-1.55 0.5,1.55, body extent -1.42,-1.46 1.42,1.46, height 1.12
DCK0005A_N [mm] "SOT353, 5-Leads, Body 2x1.3mm, Pitch 0.65mm, Lead Span 2.1mm, IPC Medium Density"
  rrect25% 0.85x0.4 smd: 1(-1.125,0.65) 2(-1.125,0) 3(-1.125,-0.65) 4(1.125,-0.65) 5(1.125,0.65)
  silkscreen extent -1.48,-1.02 0.55,1.1, body extent -1.14,-1 1.14,1, height 0.95
DRL0005A [mm] "SOTFL, 5-Flat Leads, Body 1.2x1.6x0.6mm, Pitch 0.5mm, TI recommended"
  rrect33% 0.67x0.3 smd: 1(-0.74,0.5) 2(-0.74,0) 3(-0.74,-0.5) 4(0.74,-0.5) 5(0.74,0.5)
  silkscreen extent -0.9,-0.95 0.5,0.95, body extent -0.85,-0.85 0.85,0.85, height 0.62
FCC_disclaimer [mil]
FP-M50-3900642_HDR12-MFG [mm]
  rrect9% 1.12x1.12 hole 0.65 paste-2539.97 mask+0: 1(-3.175,3)
  round 1.12 hole 0.65 paste-2539.97 mask+0: 2(-3.175,4.27) 3(-1.905,3) 4(-1.905,4.27) 5(-0.635,3) 6(-0.635,4.27) 7(0.635,3) 8(0.635,4.27) 9(1.905,3) 10(1.905,4.27) 11(3.175,3) 12(3.175,4.27)
  silkscreen extent -4.48,-0.58 4.01,3.12, body extent -4.11,-4.9 4.11,4.93, height 0.25
FP-SDEM20161T-4R7MS_SMD2-MFG [mm]
  rrect15% 0.65x1.6 smd paste+0 mask+0: 1(-0.675,0) 2(0.675,0)
  silkscreen extent -1.05,-1.22 1.05,1.2, body extent -1.15,-0.95 1.15,0.95, height 0.25
IEC_HighVoltage_Small [mil]
  silkscreen extent -107,-88 107,97
IEC_HotSurface_Small [mil]
  silkscreen extent -107,-93 107,92
Mill-Max_3621-0-32-xx-00-00-08-0 [mm] "PCB Pin, 0.04\" DIA, R/A, Edge-Mount"
  rrect50% 3.18x3.18 hole 1.65: 1(0,2.388)
  body extent -1.59,-5.06 1.59,3.98, height 1.57
RQS0052A-MFG [mm]
  rrect10% 1.05x1.05 smd paste+0 mask+0: 1(-5.675,5.2) 16(-5.675,-5.2) 27(5.675,-5.2) 42(5.675,5.2)
  rrect25% 1.05x0.4 smd paste+0 mask+0: 2(-5.675,4.225) 3(-5.675,3.575) 4(-5.675,2.925) 5(-5.675,2.275) 6(-5.675,1.625) 7(-5.675,0.975) 8(-5.675,0.325) 9(-5.675,-0.325) 10(-5.675,-0.975) 11(-5.675,-1.625) 12(-5.675,-2.275) 13(-5.675,-2.925) 14(-5.675,-3.575) 15(-5.675,-4.225) 28(5.675,-4.225) 29(5.675,-3.575) 30(5.675,-2.925) 31(5.675,-2.275) 32(5.675,-1.625) 33(5.675,-0.975) 34(5.675,-0.325) 35(5.675,0.325) 36(5.675,0.975) 37(5.675,1.625) 38(5.675,2.275) 39(5.675,2.925) 40(5.675,3.575) 41(5.675,4.225)
  rrect25% 0.4x1.05 smd paste+0 mask+0: 17(-1.935,-5.675) 18(-1.285,-5.675) 19(-0.635,-5.675) 20(0.015,-5.675) 21(0.665,-5.675) 22(1.315,-5.675) 23(1.965,-5.675) 24(2.615,-5.675) 25(3.265,-5.675) 26(3.915,-5.675) 43(3.915,5.675) 44(3.265,5.675) 45(2.615,5.675) 46(1.965,5.675) 47(1.315,5.675) 48(0.665,5.675) 49(0.015,5.675) 50(-0.635,5.675) 51(-1.285,5.675) 52(-1.935,5.675)
  silkscreen extent -6.87,-6.05 4.77,6.05, body extent -6,-6 6,6, height 1
SMB [mil] "Molded Diode, 2-Leads, Body 5.4x3.6mm, IPC Medium Density, based on OnSemi component dimensions"
  rect 85x107.99 smd: 1(-87.01,0) 2(87.01,0)
  silkscreen extent -155,-82 125,82, body extent -106,-71 106,71, height 91
SOD-123 [mm] "On Semi recommended land pattern"
  rect 0.915x1.22 smd: 1(-1.637,0) 2(1.637,0)
  silkscreen extent -2.74,-1.17 2.03,1.17, body extent -1.93,-0.9 1.93,0.9, height 1.35
TDK_ACM2520-2P [mm] "SMD, 4-Leads, Body 2.5x2mm"
  rect 0.8x0.4 smd: 1(-1.15,0.65) 2(-1.15,-0.65) 3(1.15,-0.65) 4(1.15,0.65)
  silkscreen extent -1.45,-1.2 1.45,1.4, body extent -1.35,-1.1 1.35,1.1, height 1.3
TP_H045P075#1 [mm] "TP_H0.45P0.75"
  round 4.5 / inner round 0 / far side round 4.5 hole 3.2: 1(12.68,0.479)
TP_H045P075#2 [mm] "TP_H0.45P0.75"
  round 0.75 hole 1: 1(2.26,0)
TP_H045P075#3 [mm] "TP_H0.45P0.75"
  round 0.75 hole 3.2: 1(1.005,-0.39)
TP_H045P075#4 [mm] "TP_H0.45P0.75"
  round 0.75 hole 1: 1(0,0.5)
WEEE_Minimum [mil] "WEEElie bin"
  silkscreen extent -95,-172 99,104
Wurth_760390013 [mil] "Wurth"
  rect 44x38 smd: 1(-180,100) 2(-180,0) 3(-180,-100) 4(180,-100) 5(180,0) 6(180,100)
  silkscreen extent -190,-132 85,145, body extent -198,-135 198,130, height 166

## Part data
C1 C36 C37: library part CMP-0006297-2, "CAP, CERM, 0.1 uF, 50 V, +/- 10%, X7R, 0402", Alternate Manufacturer="Wurth Elektronik", Alternate PartNumber=885012205037, Cap_Case=0402, Manufacturer=TDK, Supplier Part Number 1=445-5932-1-ND, TempCo=X7R, Tolerance_%=10%, Value1="0.039064 ohm", Value2=50V, ValueDisplayed=0.1uF
C2: library part CMP-0008020-2, "CAP, CERM, 4.7 uF, 16 V, +/- 10%, X7R, AEC-Q200 Grade 1, 0805", Cap_Case=0805, Manufacturer=MuRata, Supplier Part Number 1=490-5332-1-ND, TempCo=X7R, Tolerance_%=10%, Value1=Unknown, Value2=16V, ValueDisplayed=4.7uF
C3 C4 C13 C14 C16 C17: library part CMP-0006196-2, "CAP, CERM, 100 pF, 50 V, +/- 1%, C0G/NP0, 0402", Cap_Case=0402, Manufacturer=AVX, Supplier Part Number 1=478-3658-1-ND, TempCo=C0G/NP0, Tolerance_%=1%, Value1=Unknown, Value2=50V, ValueDisplayed=100pF
C5 C6 C7 C8 C39: library part CMP-0006276-2, "CAP, CERM, 1 uF, 25 V, +/- 10%, X5R, 0402", Alternate Manufacturer=TDK, Alternate PartNumber=C1005X5R1E225K050BC, Cap_Case=0402, Supplier Part Number 1=445-9066-1-ND, TempCo=X5R, Tolerance_%=10%, Value1=Unknown, Value2=25V, ValueDisplayed=1uF
C9 C10 C21: library part CMP-0007022-5, "CAP, CERM, 4.7 uF, 35 V, +/- 10%, X5R, 0603", Cap_Case=0603, Manufacturer=TDK, Supplier Part Number 1=445-9064-1-ND, TempCo=X5R, Tolerance_%=10%, Value1="0.003728 ohm", Value2=35V, ValueDisplayed=4.7uF
C11 C12: library part CMP-0008692-2, "CAP, CERM, 10 uF, 25 V, +/- 20%, X7R, 1206_190", Cap_Case=1206, Manufacturer=TDK, Supplier Part Number 1=445-6812-1-ND, TempCo=X7R, Tolerance_%=20%, Value1=Unknown, Value2=25V, ValueDisplayed=10uF
C15 C19: library part CMP-0860563-1, "CAP, CERM, 0.22 µF, 16 V,+/- 10%, X7R, 0402", Cap_Case=0402, Manufacturer="Samsung Electro-Mechanics", TempCo=X7R, Tolerance_%=10%, Value2=16V, ValueDisplayed=0.22µF
C18 C20: library part CMP-0006716-2, "CAP, CERM, 2.2 uF, 25 V, +/- 10%, X5R, AEC-Q200 Grade 3, 0402", Cap_Case=0402, Manufacturer=MuRata, Supplier Part Number 1=490-12267-1-ND, TempCo=X5R, Tolerance_%=10%, Value1=Unknown, Value2=25V, ValueDisplayed=2.2uF
C22 C23: library part CMP-0084048-1, "CAP, CERM, 0.022 µF, 1000 V,+/- 10%, X7R, AEC-Q200 Grade 1, 1206", Cap_Case=1206, Manufacturer=Kemet, TempCo=X7R, Tolerance_%=10%, Value2=1000V, ValueDisplayed=0.022µF
C24 C25: library part CMP-0009326-2, "CAP, CERM, 0.1 uF, 1000 V, +/- 10%, X7R, 1812", Cap_Case=1812, Manufacturer=Kemet, Supplier Part Number 1=399-6523-1-ND, TempCo=X7R, Tolerance_%=10%, Value1=Unknown, Value2=1000V, ValueDisplayed=0.1uF
C32 C33 C34 C35: library part CMP-0860835-1, "CAP, CERM, 43 pF, 50 V,+/- 5%, C0G/NP0, AEC-Q200 Grade 1, 0402", Cap_Case=0402, Manufacturer=MuRata, TempCo=C0G/NP0, Tolerance_%=5%, Value2=50V, ValueDisplayed=43pF
C38: library part CMP-0078218-1, "CAP, CERM, 0.01 µF, 16 V,+/- 10%, X7R, 0402", Cap_Case=0402, Manufacturer=Kemet, Supplier Part Number 1=399-1038-1-ND, TempCo=X7R, Tolerance_%=10%, Value2=16V, ValueDisplayed=0.01µF
D1: library part CMP-0076998-2, "Diode, Schottky, 650 V, 1 A, SMB", Manufacturer="GeneSiC Semiconductor", Value1=1A, Value2=2V
D2 D3: library part CMP-0028524-2, "Diode, Schottky, 20 V, 0.5 A, SOD-123", Manufacturer="ON Semiconductor", Value1=0.5A, Value2=0.385V
J1: library part CMP-0093439-1, "Connector Header Through Hole, Right Angle 12 position 0.050\" (1.27mm)", Current_A=1A, Digikey Part Number=952-1396-ND, Manufacturer=Harwin, Mouser Part Number=855-M50-3900642, Operating Temperature Range="-40°C to +105°C"
L1 L2: library part CMP-0089347-1, "4.7µH Unshielded Inductor 1.1A 426mOhm Max 0806 (2016 Metric)", Digikey Part Number=2037-SDEM20161T-4R7MSCT-ND, Manufacturer=Cyntec, Operating Temperature Range="-55°C to +125°C", Test Frequency=1MHz, Tolerance_%=20%
L3: library part CMP-0013161-2, "Coupled inductor, 0.2 A, 0.45 ohm, SMD", Manufacturer=TDK, Supplier Part Number 1=445-8930-1-ND
LOGO1: library part CMP-0074835-1, "IEC 61010-1 High Voltage Warning"
LOGO2: library part CMP-0074837-1, "IEC 61010-1 Hot Surface Warning"
Logo3: library part CMP-0074847-1, "FCC_disclaimer"
Logo4: library part CMP-0074769-1
Paux_RTN Paux_RTN SW SW Vbulk1 Vbulk1: library part CMP-0082316-1, "PCB Pin, 0.04\" DIA, Edge-Mount", Manufacturer=Mill-Max, Supplier Part Number 1=575-3621032150000
R1 R2 R5 R6: library part CMP-0026738-1, "RES, 49.9, 1%, 0.063 W, 0402", Manufacturer="Yageo America", Power_W=63mW, Supplier Part Number 1=311-49.9LRCT-ND, TempCo="100 ppm/C", Tolerance_%=1%, Value2=0.063W, Value_Code=49R9, ValueDisplayed=49.9
R3: library part CMP-0018623-3, "RES, 1.8, 5%, 0.25 W, AEC-Q200 Grade 0, 1206", Manufacturer=Vishay-Dale, Power_W=250mW, Supplier Part Number 1=541-1.8ECT-ND, TempCo="200 ppm/C", Tolerance_%=5%, Value2=0.25W, Value_Code=1R80, ValueDisplayed=1.8
R4 R10 R15: library part CMP-0026992-3, "RES, 0, 5%, 0.1 W, AEC-Q200 Grade 0, 0402", Manufacturer=Panasonic, Power_W=100mW, Supplier Part Number 1=P0.0JCT-ND, TempCo="600 ppm/C", Tolerance_%=5%, Value2=0.1W, Value_Code=0000, ValueDisplayed=0
R7 R9: library part CMP-0026162-1, "RES, 20.0 k, 1%, 0.063 W, 0402", Manufacturer=Vishay-Dale, Power_W=63mW, Supplier Part Number 1=541-20.0KLCT-ND, TempCo="100 ppm/C", Tolerance_%=1%, Value2=0.063W, Value_Code=20k0, ValueDisplayed=20.0k
R8: library part CMP-0018748-3, "RES, 0, 5%, 0.25 W, AEC-Q200 Grade 0, 1206", Manufacturer=Panasonic, Power_W=250mW, Supplier Part Number 1=P0.0ECT-ND, TempCo="600 ppm/C", Tolerance_%=5%, Value2=0.25W, Value_Code=0000, ValueDisplayed=0
R11 R12 R21 R22: library part CMP-0026902-3, "RES, 300, 5%, 0.063 W, AEC-Q200 Grade 0, 0402", Manufacturer=Vishay-Dale, Power_W=63mW, Supplier Part Number 1=541-300JCT-ND, TempCo="200 ppm/C", Tolerance_%=5%, Value2=0.063W, Value_Code=300R, ValueDisplayed=300
R13 R23: library part CMP-0026164-2, "RES, 20.0, 1%, 0.063 W, AEC-Q200 Grade 0, 0402", Manufacturer=Vishay-Dale, Power_W=63mW, Supplier Part Number 1=541-20.0LCT-ND, TempCo="100 ppm/C", Tolerance_%=1%, Value2=0.063W, Value_Code=20R0, ValueDisplayed=20.0
R25: library part CMP-0020803-2, "RES, 0, 5%, 0.125 W, 0805", Manufacturer="Yageo America", Power_W=125mW, Supplier Part Number 1=311-0.0ARCT-ND, TempCo="200 ppm/C", Tolerance_%=5%, Value2=0.125W, Value_Code=0000, ValueDisplayed=0
T1: library part CMP-0030718-1, "Transformer, 475uH, SMT", Manufacturer="Wurth Elektronik", Supplier Part Number 1=732-4458-1-ND, ValueDisplayed=475uH
TH1 TH2 TH3 TH4: library part CMP-0003719-1, "Testpoint", Manufacturer="Texas Instruments", PartNumber=TP_H0.45P0.75
U1: library part CMP-0076095-1, "Low-Noise 1 A, 420 kHz Transformer Driver, DBV0006A (SOT-23-6)", Alternate Manufacturer="Texas Instruments", Alternate PartNumber=SN6505BDBVT
U2 U3: library part CMP-0089510-1, Digikey Part Number=296-48140-1-ND, Manufacturer="Texas Instruments", Max Supply Voltage=5.5V, Min Supply Voltage=2.25V, Mouser Part Number=595-ISO7741FDBQR, Nominal Supply Current=0.8-18mA, Operating Temperature Range="-55°C to +125°C"
U4 U5: library part CMP-0089968-1, "650-V 30-mΩ GaN FET with Integrated Driver and Protection", Manufacturer="Texas Instruments", Max Supply Voltage=18V, Min Supply Voltage=7.5V, Nominal Supply Current=540uA, Operating Temperature Range="-40°C to +125°C", Output Voltage=520V
U6: library part CMP-0051558-2, "Single 2-Input Positive-AND Gate, DRL0005A, LARGE T&R", Alternate Manufacturer="Texas Instruments", F @ Nom Voltage(Max)(Mhz)=75, Generic Part Number=SN74AHC1G08, ICC @ Nom Voltage(Max)(mA)=0.01, Operating Temperature Range(C)="-55 to 125", Rating=Catalog, tpd @ Nom Voltage(Max)(ns)=12.3,7.9, Voltage(Nom)(V)=3.3,5
U7: library part CMP-0035674-3, "150mA, High PSRR, Low Quiescent Current, Low Noise LDO, DCK0005A (SOT-SC70-5)", Manufacturer="Texas Instruments", Operating Temperature Range="-40 to 125 C", Rating=Catalog

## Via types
v1: diameter 20, hole 10, Top Layer to Bottom Layer, 174 vias
v2: diameter 19, hole 10, Top Layer to Bottom Layer, tented both sides, 35 vias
